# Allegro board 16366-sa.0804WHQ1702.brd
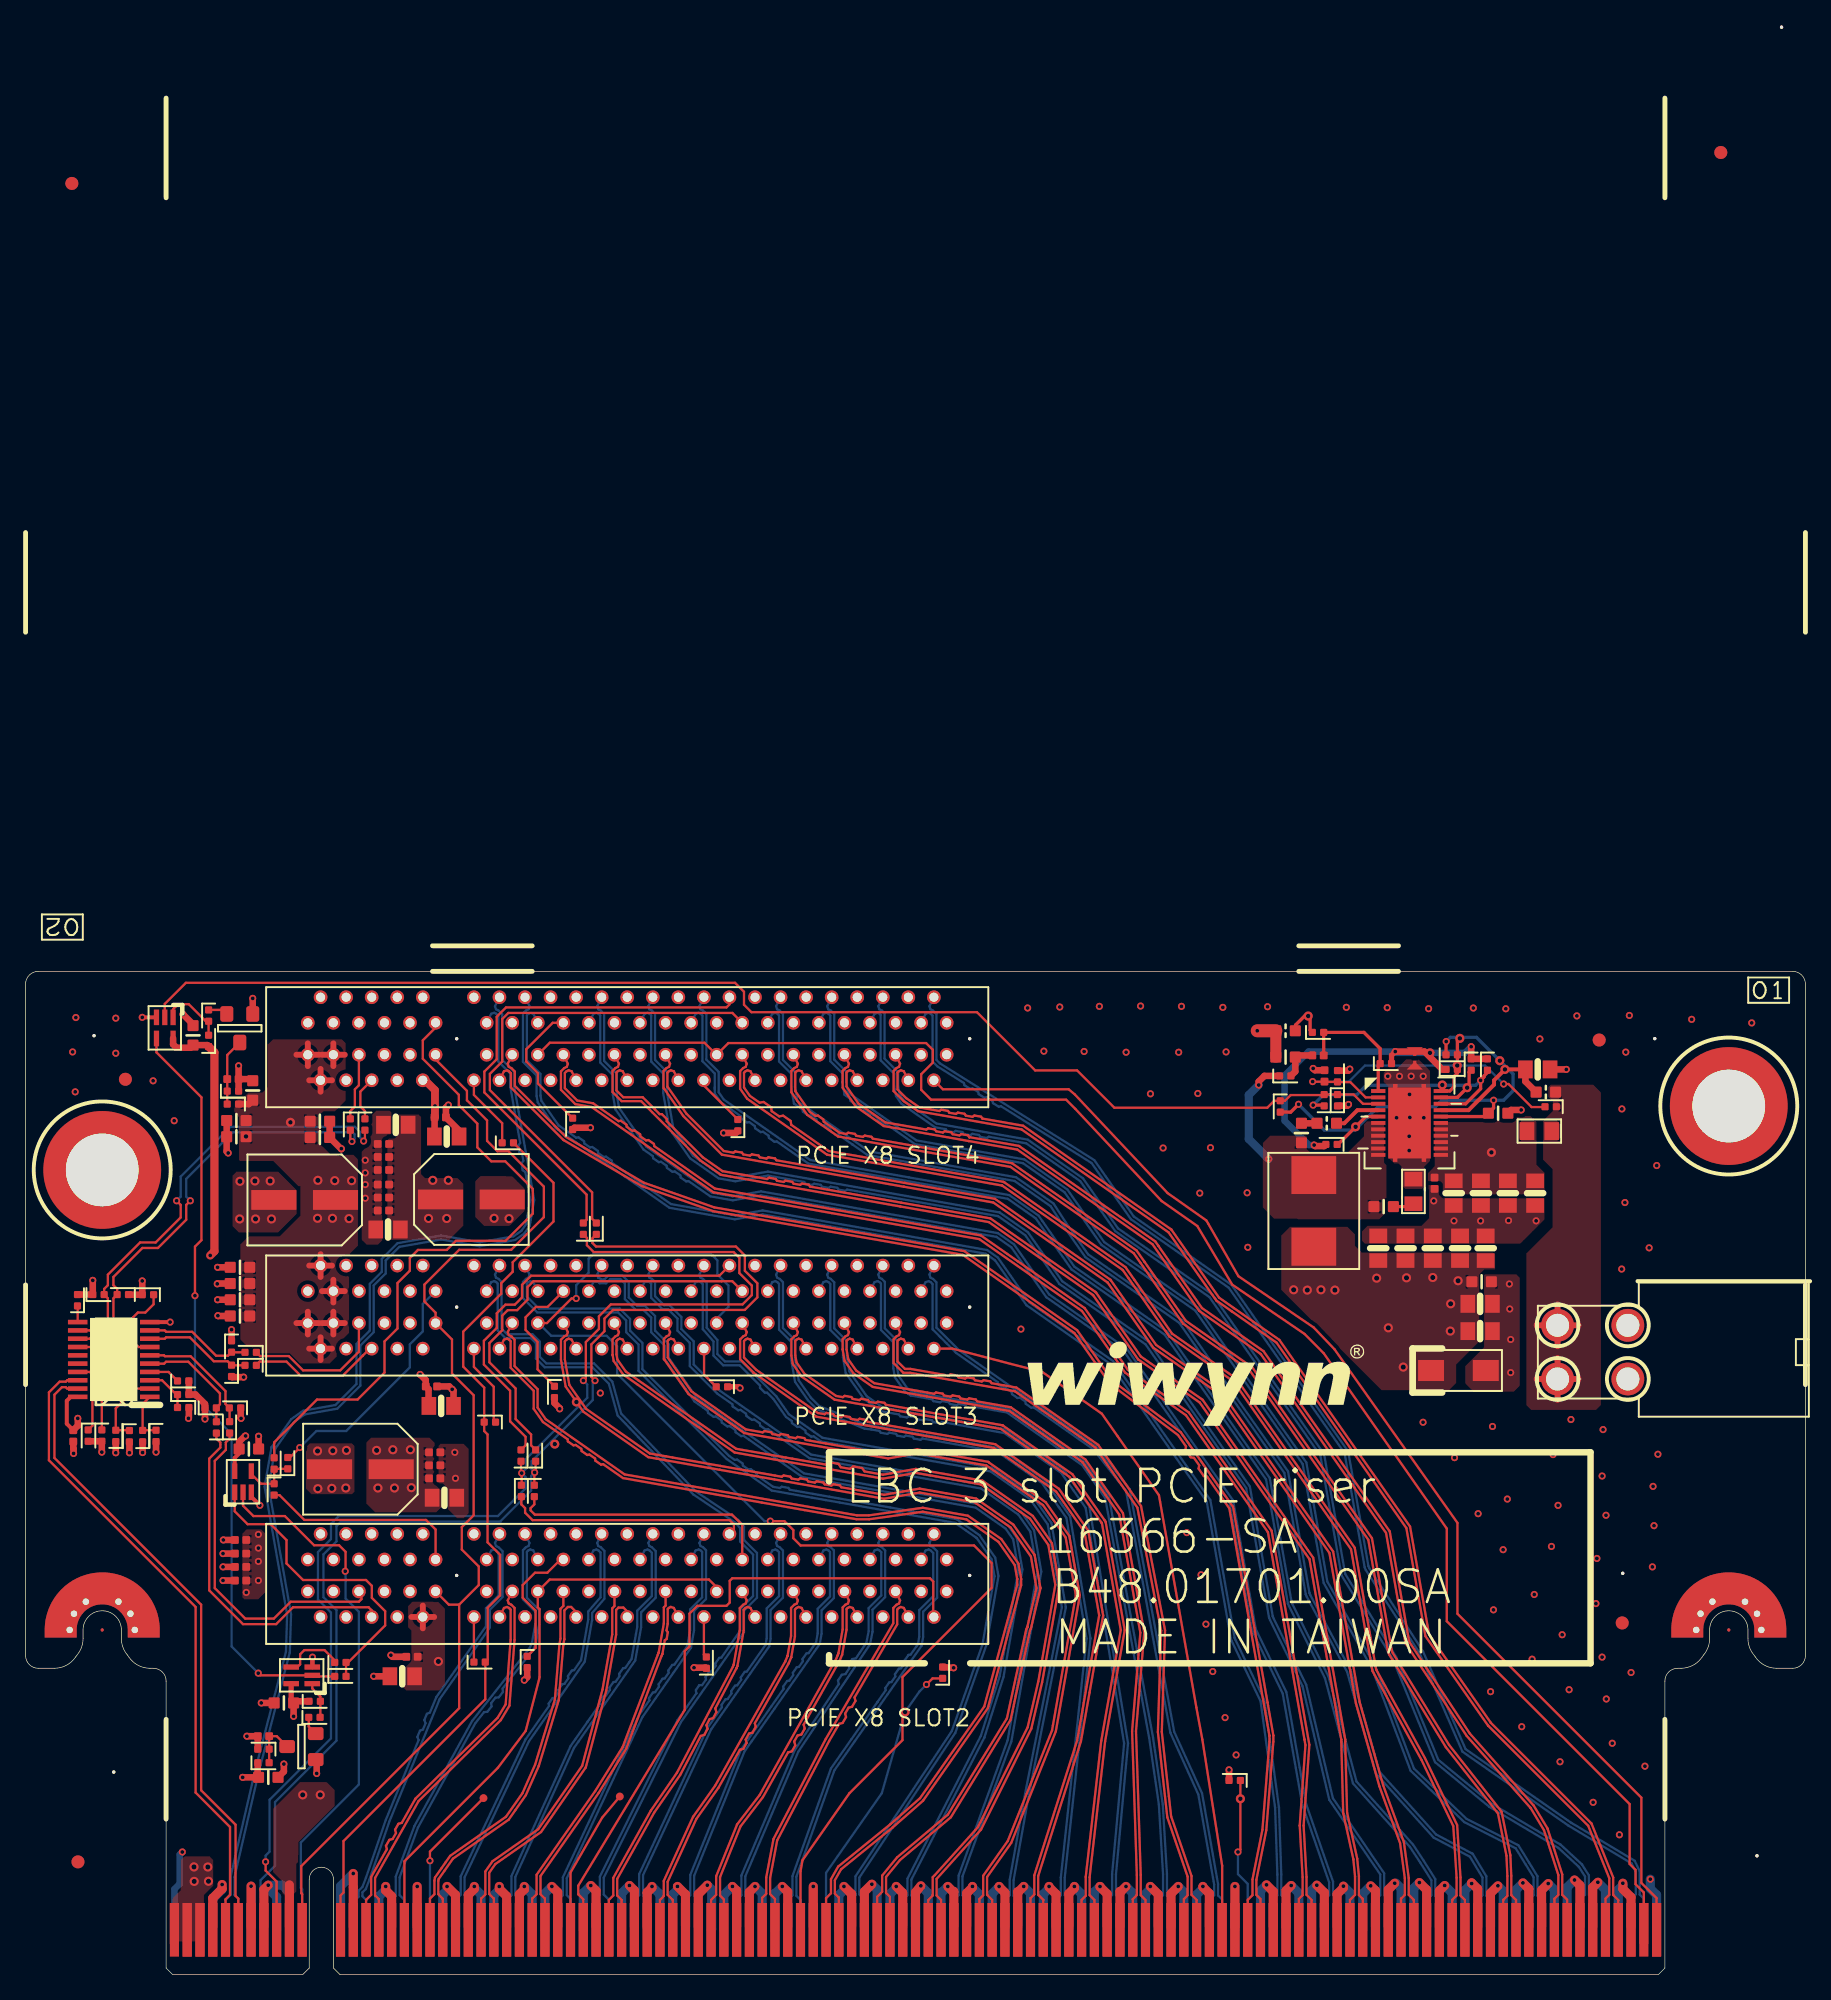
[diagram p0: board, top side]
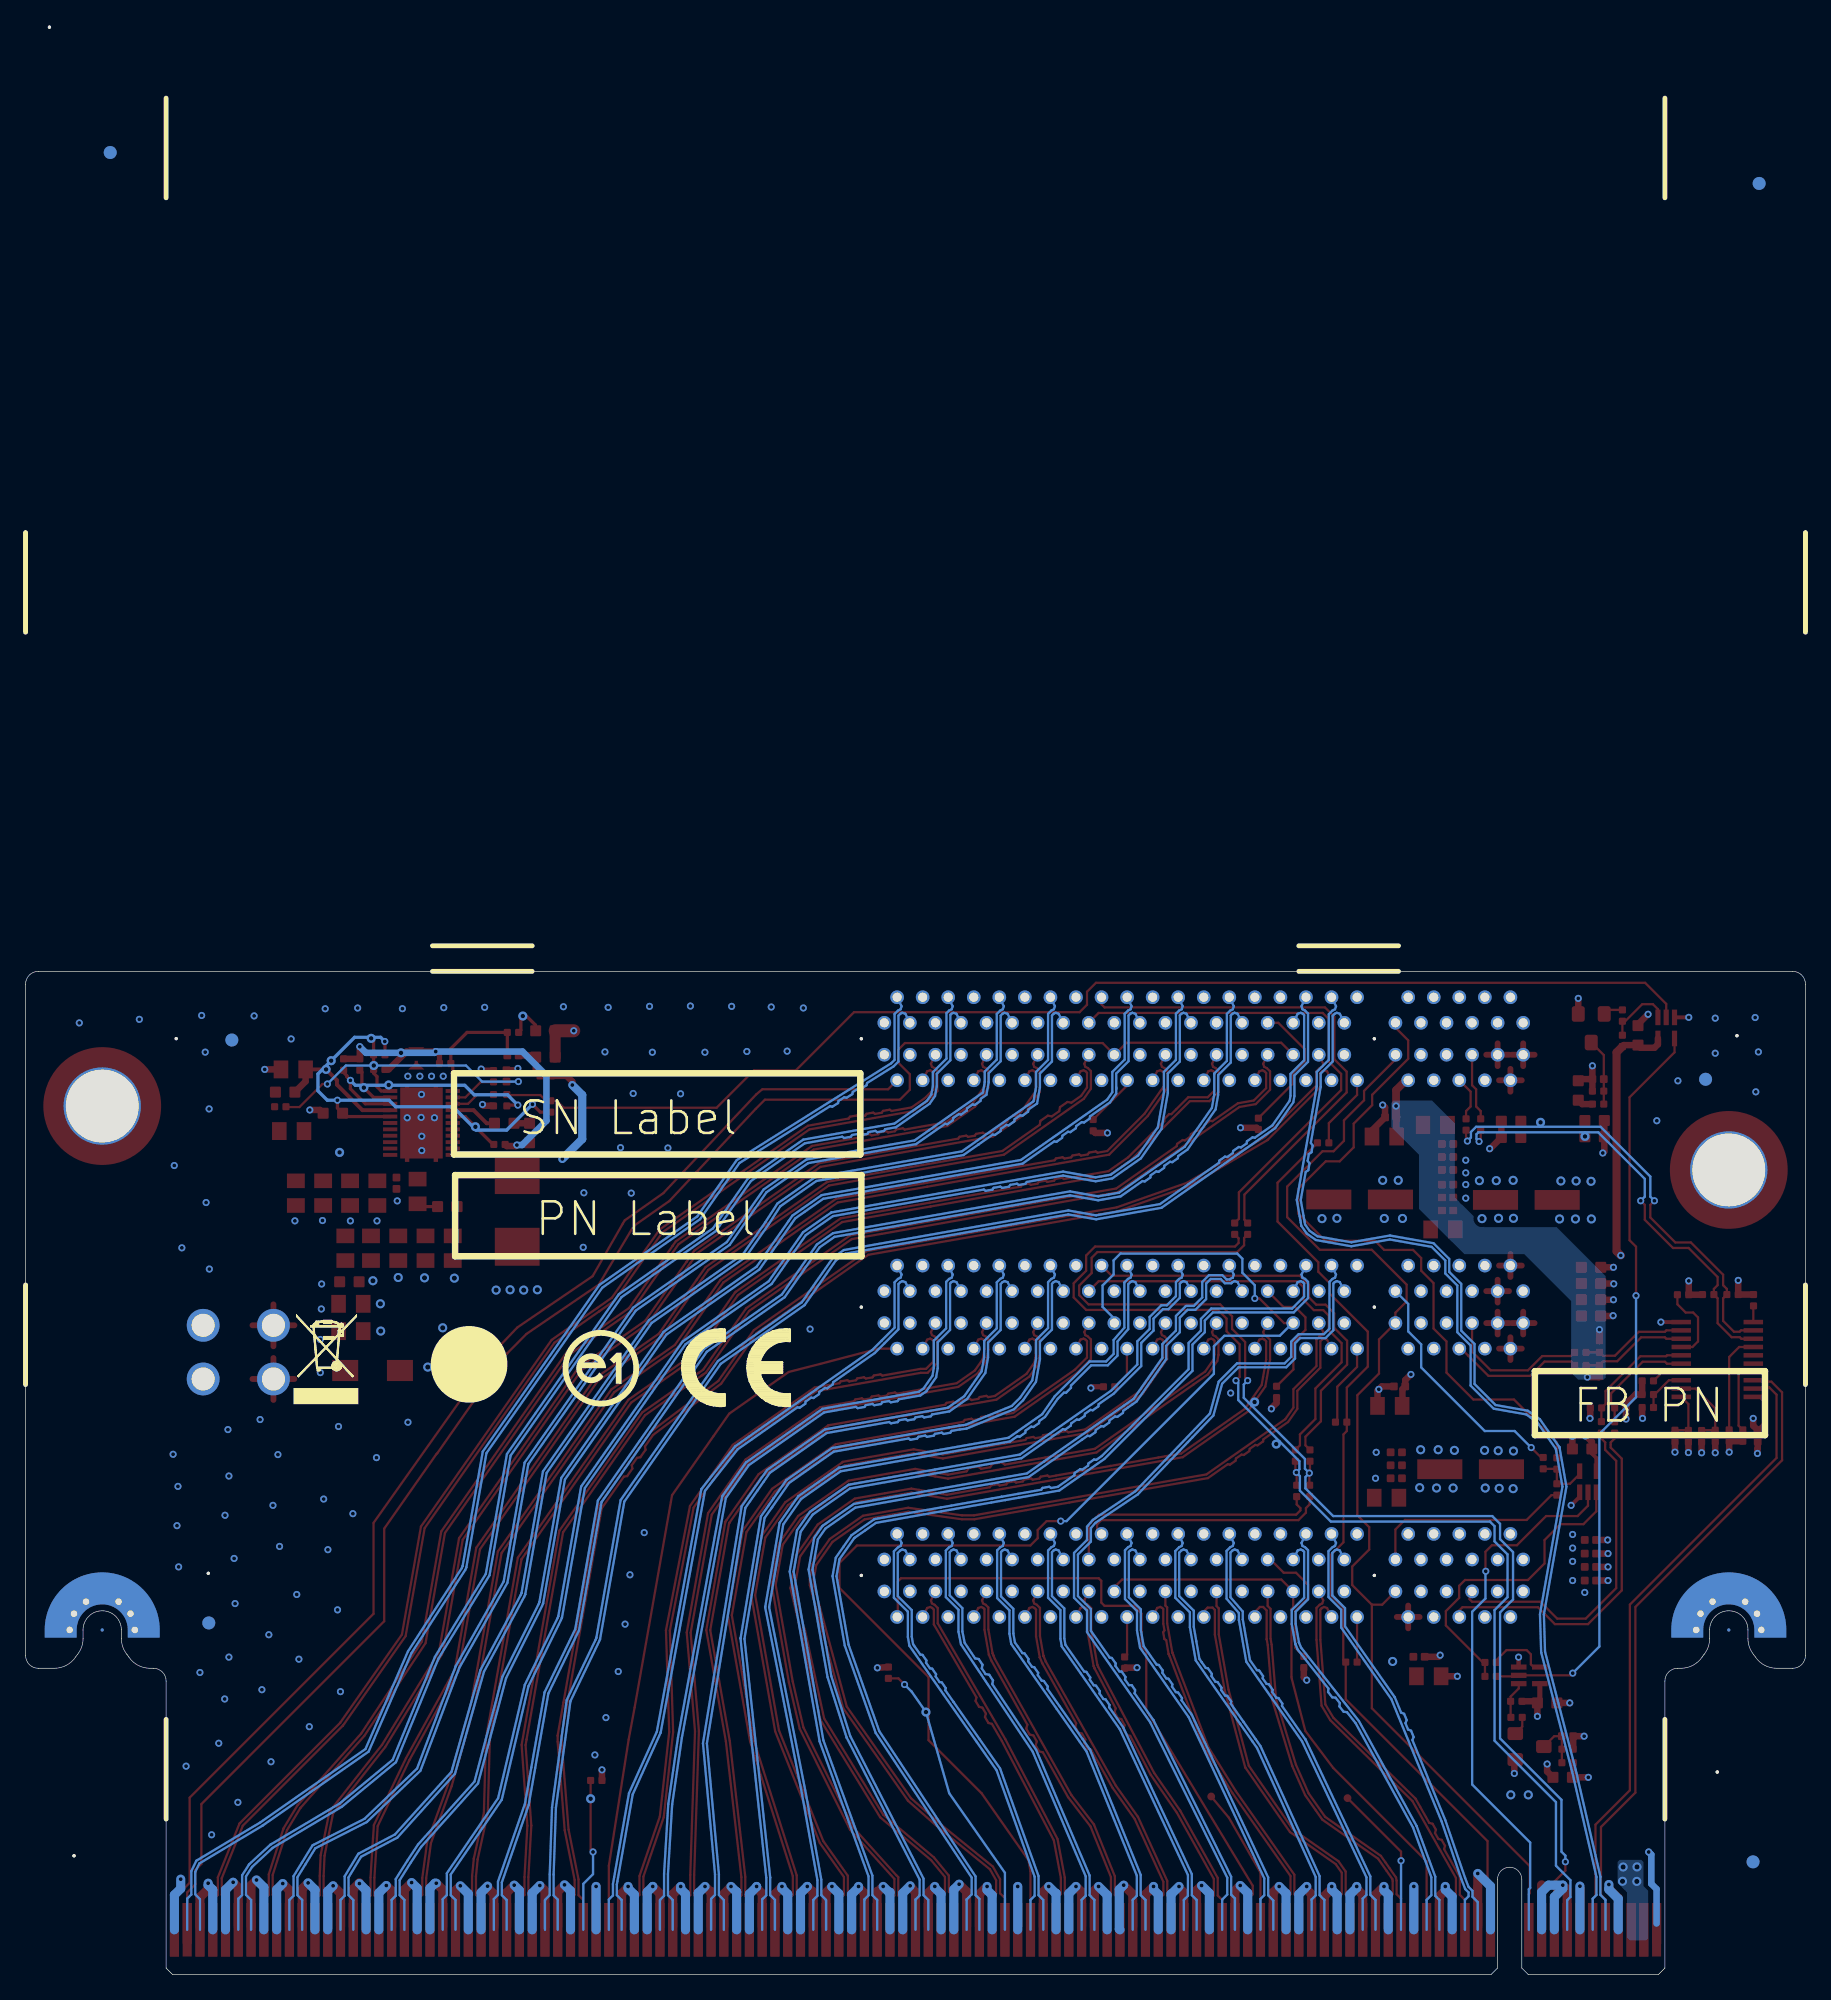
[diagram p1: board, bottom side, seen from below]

Outline 139.3 x 78.5 mm; copper layers: TOP, L2GND, L3, L4, L5GND, BOTTOM. Coordinates in mm from the lower left corner of the outline.
Outline path: 0,77.5 0,24.96 arc(0.29,24.25) 1,23.96 2.26,23.96 arc(3.2,24.2) 3.92,24.85 arc(3.99,24.94) 4.06,25.03 arc(4.39,25.62) 4.5,26.29 4.5,26.96 arc(6,28.46) 7.5,26.96 7.5,26.29 arc(7.61,25.62) 7.94,25.03 arc(8.01,24.94) 8.08,24.85 arc(8.8,24.2) 9.74,23.96 10,23.96 arc(10.71,23.67) 11,22.96 11,0.5 11.5,0 21.7,0 22.2,0.5 22.2,7.45 arc(23.15,8.4) 24.1,7.45 24.1,0.5 24.6,0 127.8,0 128.3,0.5 128.3,22.96 arc(128.59,23.67) 129.3,23.96 129.56,23.96 arc(130.5,24.2) 131.22,24.85 arc(131.29,24.94) 131.36,25.03 arc(131.69,25.62) 131.8,26.29 131.8,26.96 arc(133.3,28.46) 134.8,26.96 134.8,26.29 arc(134.91,25.62) 135.24,25.03 arc(135.31,24.94) 135.38,24.85 arc(136.1,24.2) 137.04,23.96 138.3,23.96 arc(139.01,24.25) 139.3,24.96 139.3,77.5 arc(139.01,78.21) 138.3,78.5 1,78.5 arc(0.29,78.21) 0,77.5 ; 3.2,62.96 arc(6,65.76) 8.8,62.96 arc(6,60.16) 3.2,62.96 ; 133.3,70.76 arc(136.1,67.96) 133.3,65.16 arc(130.5,67.96) 133.3,70.76

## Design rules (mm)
constraint set DEFAULT: min track width 0.127, pair gap 0.102
net group POWER_3V3: nets P3V3_SNB P3V3_VFB
net group POWER_BOOT_20_30: nets P3V3_VBST P3V3_VBST_RC
net group PWRGD_ENA_RST_50_12_12: nets P3V3_EN P3V3_PG
net group ADC_10_15: nets AGND_P3V3
net group MISC: nets ADDR_0 ADDR_1 ADDR_2 INTRPT INTRPT_0 INTRPT_1 INTRPT_2 INTRPT_3 LAN_SMB_ALERT_N PCIE_SLOT0_CPRSNT1_N PCIE_SLOT0_CPRSNT2_N PCIE_SLOT1_CPRSNT1_N PCIE_SLOT1_CPRSNT2_N PCIE_SLOT2_CPRSNT1_N PCIE_SLOT2_CPRSNT2_N PCIE_WAKE_N RSVD0 RSVD1 S0_SMB_ALERT_B12_N S1_SMB_ALERT_B12_N S2_SMB_ALERT_B12_N SLOT0_CONFIG SLOT0_ID_0 SLOT0_ID_1 SLOT1_CONFIG SLOT1_ID_0 SLOT1_ID_1 SLOT2_ID_0 SLOT2_ID_1
net group MISC_50_20_12: nets PCH_PLTRST_N PERST_O_1_R PERST_O_2_R PERST_P12V_MB_Y_N PERST_P12V_R_N PERST_P12V_Y_N PERST_SLOT0_N PERST_SLOT1_N PERST_SLOT2_N PERST_SLOT_N RESET_O_1 RESET_O_2 RESET_P12V_IN RESET_P12V_MB_IN
net group POWER_PHASE_GATE_25_20: nets P3V3_LL_R
net group POWER_SIGNAL_10_20: nets P3V3_MODE P3V3_RF P3V3_ROVP P3V3_TRIP P3V3_VFB_R P3V3_VREG
net group POWER_VCC_20_20: nets P3V3_VDD
net group PWR: nets P3V3_MB
nets with their own width: min track width 0.508; nets GND

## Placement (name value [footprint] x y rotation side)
C1  SCD1U25V2KX-GP  [C402H22]  16.83 34 270 top
C2  SCD1U25V2KX-GP  [C402H22]  16.83 32.93 270 top
C3  SCD1U25V2KX-GP  [C402H22]  16.83 31.89 270 top
C4  SCD1U25V2KX-GP  [C402H22]  16.83 30.83 270 top
C5  SCD1U16V2KX-3GP  [C402H22]  32.02 39.84 90 top
C6  SCD1U16V2KX-3GP  [C402H22]  32.02 38.83 90 top
C7  SCD1U16V2KX-3GP  [C402H22]  32.02 40.86 90 top
C8  SC10U6D3V5KX-4GP  [C805H58]  29.48 23.33 270 top
C9  SCD1U16V2KX-3GP  [C402H22]  30.24 24.86 270 top
C10  SCD1U25V3KX-GP  [C603H36]  16.78 54.07 270 top
C11  SCD1U25V3KX-GP  [C603H36]  16.78 51.53 270 top
C12  SCD1U25V3KX-GP  [C603H36]  16.78 52.8 270 top
C13  SCD1U25V3KX-GP  [C603H36]  16.78 55.34 270 top
C14  SCD1U16V2KX-3GP  [C402H22]  28.01 59.78 270 top
C15  SCD1U16V2KX-3GP  [C402H22]  28.01 61.82 270 top
C16  SCD1U16V2KX-3GP  [C402H22]  28.01 60.8 270 top
C17  SC10U6D3V5KX-4GP  [C805H58]  32.53 44.49 90 top
C18  SCD1U16V2KX-3GP  [C402H22]  31.77 46.02 90 top
C19  SCD01U16V2KX-3GP  [C402H22]  18.62 18.65 270 top
C20  SCD1U25V3KX-GP  [C603H36]  20.22 21.25 270 top
C21  SCD1U25V3KX-GP  [C603H36]  19 15.43 90 top
C22  SCD1U25V3KX-GP  [C603H36]  13.11 73.49 180 top
C23  SCD1U25V3KX-GP  [C603H36]  17.78 69.18 180 top
C24  SCD1U16V2KX-3GP  [C402H22]  3.73 42.15 180 top
C25  SCD1U25V3KX-GP  [C603H36]  16.5 66.83 270 top
C26  SCD1U16V2KX-3GP  [C402H22]  32.46 67.07 90 top
C27  SC10U6D3V5KX-4GP  [C805H58]  32.96 65.58 90 top
C28  SCD1U25V3KX-GP  [C603H36]  16.5 65.56 270 top
C29  SCD1U25V3KX-GP  [C603H36]  23.04 66.77 90 top
C30  SCD1U25V3KX-GP  [C603H36]  23.04 65.5 90 top
C31  SCD1U16V2KX-3GP  [C402H22]  28.01 63.97 270 top
C32  SCD1U16V2KX-3GP  [C402H22]  28.01 62.96 270 top
C33  SCD1U16V2KX-3GP  [C402H22]  28.01 64.99 270 top
C34  SC10U6D3V5KX-4GP  [C805H58]  32.78 37.3 90 top
C35  SC10U6D3V5KX-4GP  [C805H58]  28.37 58.3 270 top
C36  SC10U6D3V5KX-4GP  [C805H58]  28.97 66.49 270 top
C37  SCD01U16V2KX-3GP  [C402H22]  16.23 70.07 90 top
C40  SCD1U25V3KX-GP  [C603H36]  17.48 41.12 90 top
CN1  PCISLT98-79-GP  [G630H9811210TEU]  33.74 31.22 0 top
CN2  PCISLT98-79-GP  [G630H9811210TEU]  33.74 52.23 0 top
CN3  PCISLT98-79-GP  [G630H9811210TEU]  33.74 73.23 0 top
CN4  ALP-CONN4F-GP  [C23118-P04C0-L]  122.65 48.7 90 top
GF1  GF-PCIE-230P-GP  [GF-PCIE-230P]  23.15 1.4 0 top
H1  STFT363B238R224H453-GP  [STFT363B238R224H453]  6 62.96 180 top
H2  STFT363B238R224H453-GP  [STFT363B238R224H453]  133.3 67.96 180 top
H3  GEN276X162R197X296-6-F-A-GP  [GEN276X162R197X296-6-F-A]  6 26.96 0 top
H4  GEN276X162R197X296-6-F-A-GP  [GEN276X162R197X296-6-F-A]  133.3 26.96 0 top
NOREF  -  []  0 23.96 0 top
NOREF#2  *  [unnamed#2]  3.62 140.16 0 top
NOREF#3  *  [unnamed#2]  7.82 70.05 0 top
NOREF#4  *  [unnamed#2]  124.96 27.51 0 top
NOREF#5  -  []  92.02 46.21 0 top
NOREF#6  -  []  2.88 81.97 180 top
NOREF#7  -  []  0 23.96 0 top
NOREF#8  *  [unnamed#2]  4.1 8.81 0 top
NOREF#9  -  []  -5 145.85 0 top
NOREF#10  -  []  -118.09 -28.02 0 top
NOREF#11  *  [unnamed#2]  132.67 142.58 0 top
NOREF#12  -  [unnamed#2]  5.36 73.46 0 top
NOREF#13  -  []  0 23.96 0 top
NOREF#14  *  [unnamed#2]  123.16 73.13 0 top
NOREF#15  -  [unnamed#2]  127.51 73.24 0 top
NOREF#16  -  [unnamed#2]  125 31.39 0 top
NOREF#17  -  [unnamed#2]  137.43 152.39 0 top
NOREF#18  -  [unnamed#2]  135.51 9.29 0 top
NOREF#19  -  []  136.42 77.03 0 top
NOREF#20  -  [unnamed#2]  6.9 15.84 0 top
NOREF#21  -  []  87.9 47.44 180 bottom
NOREF#22  -  []  104.59 47.74 180 bottom
NOREF#23  *  [unnamed#2]  132.67 142.58 180 bottom
NOREF#24  *  [unnamed#2]  124.96 27.51 180 bottom
NOREF#25  -  []  115.79 49.07 180 bottom
NOREF#26  *  [unnamed#2]  4.1 8.81 180 bottom
NOREF#27  *  [unnamed#2]  7.82 70.05 180 bottom
NOREF#28  *  [unnamed#2]  123.16 73.13 180 bottom
NOREF#29  -  []  94.28 47.44 180 bottom
NOREF#30  *  [unnamed#2]  3.62 140.16 180 bottom
PC485  SC470P50V2KX-3GP  [C402H22]  101.15 71.92 90 top
PC790  SC22U6D3V5MX-5-GP  [C805H56]  105.87 56.83 180 top
PC792  SC22U6D3V5MX-5-GP  [C805H56]  108 56.83 180 top
PC793  SC22U6D3V5MX-5-GP  [C805H56]  110.13 56.83 180 top
PC794  SC22U6D3V5MX-5-GP  [C805H56]  112.27 56.83 180 top
PC795  SC22U6D3V5MX-5-GP  [C805H56]  114.27 56.83 180 top
PC836  SC22U6D3V5MX-5-GP  [C805H56]  113.84 52.48 90 top
PC904  SC10U16V5KX-1-GP  [C805H54]  116.01 61.14 0 top
PC905  SC10U16V5KX-1-GP  [C805H54]  118.14 61.14 0 top
PC906  SC10U16V5KX-1-GP  [C805H54]  111.77 61.14 0 top
PC907  SCD1U16V2KX-3GP  [C402H22]  110.27 61.92 0 top
PC908  SCD1U16V3KX-3GP  [C603H36]  113.96 54.21 90 top
PC909  SC22U6D3V5MX-5-GP  [C805H56]  113.84 50.35 90 top
PC911  SC10U16V5KX-1-GP  [C805H54]  113.9 61.14 0 top
PC917  SCD1U50V3KX-GP  [C603H36]  99.86 65.85 0 top
PC918  SC2K2P50V3KX-GP  [C603]  106.29 60.09 90 top
PC919  SCD1U50V3KX-GP  [C603H36]  98.61 71.79 90 top
PC941  SC4D7U25V5KX-1-GP  [C805H58]  118.35 70.83 90 top
PC942  SC1U16V3KX-5GP  [C603H36]  115.25 67.4 270 top
PC1055  SC1U10V2KX-4-GP  [C402H22]  101.66 70.32 180 top
PD11  PTZ5D6B-GP  [D502715AKH87]  112.14 47.26 270 top
PG64  COPPER-CLOSE-GP-U  [CON2C-U]  108.72 71.69 0 top
PL49  IND-1UH-188-GP  [L7166-1830-UH197]  100.82 59.75 0 top
PL50  BLM21PG220SN1DGP  [L20125H42]  118.47 66 270 top
PR2  147KR2F-L-GP  [R402H16]  113.14 71.21 0 top
PR3  309KR2F-GP  [R402H16]  111.62 71.97 90 top
PR4  309KR2F-GP  [R402H16]  111.62 70.83 90 top
PR36  3K74R2F-GP  [R402H16]  102.68 70.29 180 top
PR347  20KR2F-L-GP  [R402H16]  102.68 68.41 180 top
PR441  10KR2F-2-GP  [R402H16]  98.2 67.93 0 top
PR481  2D7R3-GP  [R603H22]  101.84 66.61 270 top
PR540  19K6R2F-GP  [R402H16]  119.36 67.91 270 top
PR633  10R3F-GP  [R603H22]  98.61 73.85 90 top
PR635  45K3R2F-L-GP  [R402H16]  101.15 73.72 90 top
PR638  10KR2F-2-GP  [R402H16]  106.46 71.28 90 top
PR640  2KR2F-3-GP  [R402H16]  98.59 70.32 90 top
PR642  3D01R5F-GP  [R805H24]  108.62 61.28 180 top
PR649  2D2R3-1-U-GP  [R603H22]  118.98 69.05 270 top
PR817  0R2J-2-GP  [R402H16]  102.21 64.96 270 top
PR2171  39K2R2F-L-GP  [R402H16]  114.41 71.21 0 top
PR2172  39K2R2F-L-GP  [R402H16]  101.63 68.41 180 top
PU54  TPS53319DQPR-GP  [QFN22G6050-G6133H60]  108.31 66.64 90 top
R1  8K2R2F-1-GP  [R402H16]  18.62 16.57 90 top
R2  3K3R2F-2-GP  [R402H16]  18.62 17.63 270 top
R3  0R2J-2-GP  [R402H16]  22.61 20.12 90 top
R4  0R2J-2-GP  [R402H16]  14.33 75.04 0 top
R5  8K2R2F-1-GP  [R402H16]  16.23 68.11 270 top
R7  100R2J-L-GP  [R402H15]  39.26 24.45 0 top
R8  100R2J-L-GP  [R402H15]  53.28 24.4 180 top
R9  100R2J-L-GP  [R402H15]  54.5 45.99 270 top
R10  100R2J-L-GP  [R402H15]  41.39 45.59 0 top
R11  100R2J-L-GP  [R402H15]  55.74 66.46 180 top
R12  100R2J-L-GP  [R402H15]  42.82 66.57 0 top
R13  10KR2F-2-GP  [R402H16]  12.34 46.45 90 top
R14  10KR2F-2-GP  [R402H16]  9.58 53.2 270 top
R15  10KR2F-2-GP  [R402H16]  4.06 52.76 180 top
R16  10KR2F-2-GP  [R402H16]  5.97 42.17 0 top
R17  10KR2F-2-GP  [R402H16]  4.9 42.17 0 top
R18  4K7R2J-2-GP  [R402H16]  16.39 44.34 270 top
R19  4K7R2J-2-GP  [R402H16]  16.12 49.14 0 top
R20  4K7R2J-2-GP  [R402H16]  7.61 53.21 270 top
R21  4K7R2J-2-GP  [R402H16]  14.49 44.34 90 top
R22  4K7R2J-2-GP  [R402H16]  16.12 47.24 180 top
R23  4K7R2J-2-GP  [R402H16]  5.71 53.21 90 top
R24  3K3R2F-2-GP  [R402H16]  16.23 69.13 90 top
R26  10KR2F-2-GP  [R402H16]  12.34 44.37 270 top
R27  10KR2F-2-GP  [R402H16]  7.06 42.15 180 top
R28  10KR2F-2-GP  [R402H16]  9.16 42.13 180 top
R29  10KR2F-2-GP  [R402H16]  10.21 42.15 0 top
R30  10KR2F-2-GP  [R402H16]  8.13 42.12 0 top
R31  10KR2F-2-GP  [R402H16]  12.34 45.38 90 top
R33  1KR2J-1-GP  [R402H16]  71.77 23.61 180 top
R35  1KR2J-1-GP  [R402H16]  94.63 15.18 270 top
R36  4K7R2J-2-GP  [R402H16]  14.33 73.06 180 top
R37  4K7R2J-2-GP  [R402H16]  22.63 21.38 90 top
R38  0R2J-2-GP  [R402H16]  20.52 40.01 180 top
R39  0R2J-2-GP  [R402H16]  19.46 37.96 0 top
R40  0R2J-2-GP  [R402H16]  19.46 39.99 180 top
R41  0R2J-2-GP  [R402H16]  24.64 24.42 90 top
R42  0R2J-2-GP  [R402H16]  24.64 23.33 90 top
RE1  0R2J-2-GP  [R402H16]  15.97 42.82 180 top
RE2  0R2J-2-GP  [R402H16]  38.8 37.84 0 top
RE3  0R2J-2-GP  [R402H16]  39.82 37.84 0 top
RE4  0R2J-2-GP  [R402H16]  35.53 24.44 90 top
RE5  0R2J-2-GP  [R402H16]  36.34 43.22 270 top
RE6  0R2J-2-GP  [R402H16]  17.62 48.68 270 top
RE7  0R2J-2-GP  [R402H16]  14.94 42.81 180 top
RE8  0R2J-2-GP  [R402H16]  17.62 47.67 270 top
RE9  0R2J-2-GP  [R402H16]  38.78 40.61 180 top
RE10  0R2J-2-GP  [R402H16]  39.92 40.61 180 top
RE11  0R2J-2-GP  [R402H16]  37.74 65.08 90 top
RE12  0R2J-2-GP  [R402H16]  25.42 66.51 0 top
RE13  0R2J-2-GP  [R402H16]  26.56 66.51 0 top
RE14  0R2J-2-GP  [R402H16]  43.65 58.36 180 top
RE15  0R2J-2-GP  [R402H16]  44.67 58.36 180 top
TC1  SE100U16VM-10GP  [SE351618H217]  21.84 60.61 270 top
TC2  SE100U16VM-10GP  [SE351618H217]  34.89 60.65 90 top
TC3  SE100U16VM-10GP  [SE351618H217]  26.2 39.54 270 top
TP6  -  [TPAD24]  46.51 13.93 0 top
TP7  -  [TPAD24]  35.84 13.8 0 top
U1  TPS3809K33-2-GP  [SOT-23-1H58]  21.59 17.83 90 top
U2  TPS3809K33-2-GP  [SOT-23-1H58]  16.76 74.05 180 top
U8  SNLVC1G08DCKRG4-GP  [SC70-5H44]  21.61 23.41 270 top
U9  SNLVC1G08DCKRG4-GP  [SC70-5H44]  10.9 74.07 0 top
U10  PCA9544APW-GP  [TSOIC20H44]  6.9 48.13 90 top
U13  SNLVC1G08DCKRG4-GP  [SC70-5H44]  17.02 38.56 180 top

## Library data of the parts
C1-C4 = C402H22: tolerance: 78.10422.5FL
C5-C7 C9 C14-C16 C18 C24 C26 C31-C33 PC907 = C402H22: tolerance: 78.10421.2FL
C8 C17 C27 C34-C36 = C805H58: tolerance: 78.10620.21L
C10-C13 C20-C23 C25 C28-C30 C40 = C603H36: tolerance: 78.10422.2BL
C19 C37 = C402H22: tolerance: 78.10321.2FL
CN1-CN3 = G630H9811210TEU: tolerance: 020.50107.0098
CN4 = C23118-P04C0-L: tolerance: 020.80390.0004
GF1 = GF-PCIE-230P: tolerance: ZZ.GF001.711; alternate symbols: (TOP:GF-PCIE-230P)
H1 H2 = STFT363B238R224H453: tolerance: 086.2AT24.04R6
H3 H4 = GEN276X162R197X296-6-F-A: tolerance: ZZ.SCREW.511
PC485 = C402H22: tolerance: 78.47124.2FL
PC790 PC792-PC795 PC836 PC909 = C805H56: tolerance: 78.22610.81L
PC904-PC906 PC911 = C805H54: tolerance: 78.10621.81L
PC908 = C603H36: tolerance: 78.10421.2BL
PC917 PC919 = C603H36: tolerance: 78.10424.2BL
PC918 = C603: tolerance: 78.22224.2BL
PC941 = C805H58: tolerance: 078.47522.0211
PC942 = C603H36: tolerance: 78.10521.2BL
PC1055 = C402H22: tolerance: 78.10523.8FL
PD11 = D502715AKH87: tolerance: 83.5R603.H3H
PG64 = CON2C-U: tolerance: ZZ.CON2C.XXX
PL49 = L7166-1830-UH197: tolerance: 68.1R01E.10D
PL50 = L20125H42: tolerance: 68.00084.831
PR2 = R402H16: tolerance: 64.14735.L1L
PR3 PR4 = R402H16: tolerance: 64.30935.6DL
PR36 = R402H16: tolerance: 64.37415.6DL
PR347 = R402H16: tolerance: 64.20025.6DL
PR441 PR638 R13-R17 R26-R31 = R402H16: tolerance: 64.10025.6DL
PR481 = R603H22: tolerance: 63.2R734.15L
PR540 = R402H16: tolerance: 64.19625.6DL
PR633 = R603H22: tolerance: 64.10R05.55L
PR635 = R402H16: tolerance: 64.45325.6DL
PR640 = R402H16: tolerance: 64.20015.6DL
PR642 = R805H24: tolerance: 64.3R015.16L
PR649 = R603H22: tolerance: 64.2R205.55L
PR817 R3 R4 R38-R42 RE1-RE15 = R402H16: tolerance: 63.R0034.1DL
PR2171 PR2172 = R402H16: tolerance: 64.39225.6DL
PU54 = QFN22G6050-G6133H60: tolerance: 74.53319.073
R1 R5 = R402H16: tolerance: 64.82015.6DL
R2 R24 = R402H16: tolerance: 64.33015.6DL
R7-R12 = R402H15: tolerance: 63.10134.L0L
R18-R23 R36 R37 = R402H16: tolerance: 63.47234.1DL
R33 R35 = R402H16: tolerance: 63.10234.1DL
TC1-TC3 = SE351618H217: tolerance: 79.1071D.3AL
TP6 TP7 = TPAD24: tolerance: ZZ.PAD24.001
U1 U2 = SOT-23-1H58: tolerance: 74.03809.07B
U8 U9 U13 = SC70-5H44: tolerance: 73.01G08.DHG
U10 = TSOIC20H44: tolerance: 71.09544.A0W

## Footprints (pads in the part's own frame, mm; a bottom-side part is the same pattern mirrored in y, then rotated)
C402H22
  custom 0.152x0.152 smd: 1(0,0.445) 2(0,-0.445)
C603
  custom 0.216x0.216 smd: 1(0,0.762) 2(0,-0.762)
C603H36
  custom 0.216x0.216 smd: 1(0,0.762) 2(0,-0.762)
C805H54
  rect 1.397x1.143 smd: 1(0,0.965) 2(0,-0.965)
C805H56
  rect 1.397x1.143 smd: 1(0,0.965) 2(0,-0.965)
C805H58
  rect 1.397x1.143 smd: 1(0,0.965) 2(0,-0.965)
C23118-P04C0-L
  round 2.565 hole 1.803: 1(2.1,-2.75) 2(-2.1,-2.75) 3(2.1,2.75) 4(-2.1,2.75)
CON2C-U
  custom 0.171x0.171 smd: 1(0,0.533) 2(0,-0.533)
D502715AKH87
  rect 1.651x2.032 smd: A(0,2.142) K(0,-2.142)
G630H9811210TEU
  round 0.254 hole 2.362 unplated: (0,0) (40.15,0)
  round 1.067 hole 0.711: A1(-11.65,1.25) A2(-10.65,3.25) A3(-9.65,1.25) A4(-8.65,3.25) A5(-7.65,1.25) A6(-6.65,3.25) A7(-5.65,1.25) A8(-4.65,3.25) A9(-3.65,1.25) A10(-2.65,3.25) A11(-1.65,1.25) A12(1.35,3.25) A13(2.35,1.25) A14(3.35,3.25) A15(4.35,1.25) A16(5.35,3.25) A17(6.35,1.25) A18(7.35,3.25) A19(8.35,1.25) A20(9.35,3.25) A21(10.35,1.25) A22(11.35,3.25) A23(12.35,1.25) A24(13.35,3.25) A25(14.35,1.25) A26(15.35,3.25) A27(16.35,1.25) A28(17.35,3.25) A29(18.35,1.25) A30(19.35,3.25) A31(20.35,1.25) A32(21.35,3.25) A33(22.35,1.25) A34(23.35,3.25) A35(24.35,1.25) A36(25.35,3.25) A37(26.35,1.25) A38(27.35,3.25) A39(28.35,1.25) A40(29.35,3.25) A41(30.35,1.25) A42(31.35,3.25) A43(32.35,1.25) A44(33.35,3.25) A45(34.35,1.25) A46(35.35,3.25) A47(36.35,1.25) A48(37.35,3.25) A49(38.35,1.25) B1(-11.65,-1.25) B2(-10.65,-3.25) B3(-9.65,-1.25) B4(-8.65,-3.25) B5(-7.65,-1.25) B6(-6.65,-3.25) B7(-5.65,-1.25) B8(-4.65,-3.25) B9(-3.65,-1.25) B10(-2.65,-3.25) B11(-1.65,-1.25) B12(1.35,-3.25) B13(2.35,-1.25) B14(3.35,-3.25) B15(4.35,-1.25) B16(5.35,-3.25) B17(6.35,-1.25) B18(7.35,-3.25) B19(8.35,-1.25) B20(9.35,-3.25) B21(10.35,-1.25) B22(11.35,-3.25) B23(12.35,-1.25) B24(13.35,-3.25) B25(14.35,-1.25) B26(15.35,-3.25) B27(16.35,-1.25) B28(17.35,-3.25) B29(18.35,-1.25) B30(19.35,-3.25) B31(20.35,-1.25) B32(21.35,-3.25) B33(22.35,-1.25) B34(23.35,-3.25) B35(24.35,-1.25) B36(25.35,-3.25) B37(26.35,-1.25) B38(27.35,-3.25) B39(28.35,-1.25) B40(29.35,-3.25) B41(30.35,-1.25) B42(31.35,-3.25) B43(32.35,-1.25) B44(33.35,-3.25) B45(34.35,-1.25) B46(35.35,-3.25) B47(36.35,-1.25) B48(37.35,-3.25) B49(38.35,-1.25)
GEN276X162R197X296-6-F-A
  round 0.254 hole 0.025 unplated: (0,0)
  round 0.864 hole 0.508: 1(2.55,0) 2(2.21,1.27) 3(1.27,2.21) 4(-1.28,2.21) 5(-2.21,1.27) 6(-2.55,0)
GF-PCIE-230P
  rect 0.711x3.2 smd: A1(-11.5,2.591) B114(103.5,2.591)
  rect 0.711x4.191 smd: A2(-10.5,2.095) A3(-9.5,2.095) A4(-8.5,2.095) A5(-7.5,2.095) A6(-6.5,2.095) A7(-5.5,2.095) A8(-4.5,2.095) A9(-3.5,2.095) A10(-2.5,2.095) A11(-1.5,2.095) A12(1.5,2.095) A13(2.5,2.095) A14(3.5,2.095) A15(4.5,2.095) A16(5.5,2.095) A17(6.5,2.095) A18(7.5,2.095) A19(8.5,2.095) A20(9.5,2.095) A21(10.5,2.095) A22(11.5,2.095) A23(12.5,2.095) A24(13.5,2.095) A25(14.5,2.095) A26(15.5,2.095) A27(16.5,2.095) A28(17.5,2.095) A29(18.5,2.095) A30(19.5,2.095) A31(20.5,2.095) A32(21.5,2.095) A33(22.5,2.095) A34(23.5,2.095) A35(24.5,2.095) A36(25.5,2.095) A37(26.5,2.095) A38(27.5,2.095) A39(28.5,2.095) A40(29.5,2.095) A41(30.5,2.095) A42(31.5,2.095) A43(32.5,2.095) A44(33.5,2.095) A45(34.5,2.095) A46(35.5,2.095) A47(36.5,2.095) A48(37.5,2.095) A49(38.5,2.095) A50(39.5,2.095) A51(40.5,2.095) A52(41.5,2.095) A53(42.5,2.095) A54(43.5,2.095) A55(44.5,2.095) A56(45.5,2.095) A57(46.5,2.095) A58(47.5,2.095) A59(48.5,2.095) A60(49.5,2.095) A61(50.5,2.095) A62(51.5,2.095) A63(52.5,2.095) A64(53.5,2.095) A65(54.5,2.095) A66(55.5,2.095) A67(56.5,2.095) A68(57.5,2.095) A69(58.5,2.095) A70(59.5,2.095) A71(60.5,2.095) A72(61.5,2.095) A73(62.5,2.095) A74(63.5,2.095) A75(64.5,2.095) A76(65.5,2.095) A77(66.5,2.095) A78(67.5,2.095) A79(68.5,2.095) A80(69.5,2.095) A81(70.5,2.095) A82(71.5,2.095) A83(72.5,2.095) A84(73.5,2.095) A85(74.5,2.095) A86(75.5,2.095) A87(76.5,2.095) A88(77.5,2.095) A89(78.5,2.095) A90(79.5,2.095) A91(80.5,2.095) A92(81.5,2.095) A93(82.5,2.095) A94(83.5,2.095) A95(84.5,2.095) A96(85.5,2.095) A97(86.5,2.095) A98(87.5,2.095) A99(88.5,2.095) A100(89.5,2.095) A101(90.5,2.095) A102(91.5,2.095) A103(92.5,2.095) A104(93.5,2.095) A105(94.5,2.095) A106(95.5,2.095) A107(96.5,2.095) A108(97.5,2.095) A109(98.5,2.095) A110(99.5,2.095) A111(100.5,2.095) A112(101.5,2.095) A113(102.5,2.095) A114(103.5,2.095) A115(104.5,2.095) B1(-11.5,2.349) B2(-10.5,2.349) B3(-9.5,2.349) B4(-8.5,2.349) B5(-7.5,2.349) B6(-6.5,2.349) B7(-5.5,2.349) B8(-4.5,2.349) B9(-3.5,2.349) B10(-2.5,2.349) B11(-1.5,2.349) B12(1.5,2.349) B13(2.5,2.349) B14(3.5,2.349) B15(4.5,2.349) B16(5.5,2.349) B17(6.5,2.349) B18(7.5,2.349) B19(8.5,2.349) B20(9.5,2.349) B21(10.5,2.349) B22(11.5,2.349) B23(12.5,2.349) B24(13.5,2.349) B25(14.5,2.349) B26(15.5,2.349) B27(16.5,2.349) B28(17.5,2.349) B29(18.5,2.349) B30(19.5,2.349) B31(20.5,2.349) B32(21.5,2.349) B33(22.5,2.349) B34(23.5,2.349) B35(24.5,2.349) B36(25.5,2.349) B37(26.5,2.349) B38(27.5,2.349) B39(28.5,2.349) B40(29.5,2.349) B41(30.5,2.349) B42(31.5,2.349) B43(32.5,2.349) B44(33.5,2.349) B45(34.5,2.349) B46(35.5,2.349) B47(36.5,2.349) B48(37.5,2.349) B49(38.5,2.349) B50(39.5,2.349) B51(40.5,2.349) B52(41.5,2.349) B53(42.5,2.349) B54(43.5,2.349) B55(44.5,2.349) B56(45.5,2.349) B57(46.5,2.349) B58(47.5,2.349) B59(48.5,2.349) B60(49.5,2.349) B61(50.5,2.349) B62(51.5,2.349) B63(52.5,2.349) B64(53.5,2.349) B65(54.5,2.349) B66(55.5,2.349) B67(56.5,2.349) B68(57.5,2.349) B69(58.5,2.349) B70(59.5,2.349) B71(60.5,2.349) B72(61.5,2.349) B73(62.5,2.349) B74(63.5,2.349) B75(64.5,2.349) B76(65.5,2.349) B77(66.5,2.349) B78(67.5,2.349) B79(68.5,2.349) B80(69.5,2.349) B81(70.5,2.349) B82(71.5,2.349) B83(72.5,2.349) B84(73.5,2.349) B85(74.5,2.349) B86(75.5,2.349) B87(76.5,2.349) B88(77.5,2.349) B89(78.5,2.349) B90(79.5,2.349) B91(80.5,2.349) B92(81.5,2.349) B93(82.5,2.349) B94(83.5,2.349) B95(84.5,2.349) B96(85.5,2.349) B97(86.5,2.349) B98(87.5,2.349) B99(88.5,2.349) B100(89.5,2.349) B101(90.5,2.349) B102(91.5,2.349) B103(92.5,2.349) B104(93.5,2.349) B105(94.5,2.349) B106(95.5,2.349) B107(96.5,2.349) B108(97.5,2.349) B109(98.5,2.349) B110(99.5,2.349) B111(100.5,2.349) B112(101.5,2.349) B113(102.5,2.349) B115(104.5,2.349)
L7166-1830-UH197
  rect 3.505x2.972 smd: 1(0,2.805) 2(0,-2.805)
L20125H42
  rect 1.397x1.143 smd: 1(0,0.965) 2(0,-0.965)
QFN22G6050-G6133H60
  rect 0.305x1.118 smd: 1(2.5,2.449) 2(2,2.449) 3(1.5,2.449) 4(1,2.449) 5(0.5,2.449) 6(0,2.449) 7(-0.5,2.449) 8(-1,2.449) 9(-1.5,2.449) 10(-2,2.449) 11(-2.5,2.449) 12(-2.5,-2.449) 13(-2,-2.449) 14(-1.5,-2.449) 15(-1,-2.449) 16(-0.5,-2.449) 17(0,-2.449) 18(0.5,-2.449) 19(1,-2.449) 20(1.5,-2.449) 21(2,-2.449) 22(2.5,-2.449)
  custom 0.832x0.832 smd: 23(0,0)
R402H15
  custom 0.14x0.14 smd: 1(0,0.445) 2(0,-0.445)
R402H16
  custom 0.14x0.14 smd: 1(0,0.445) 2(0,-0.445)
R603H22
  custom 0.216x0.216 smd: 1(0,0.762) 2(0,-0.762)
R805H24
  rect 1.397x1.143 smd: 1(0,0.965) 2(0,-0.965)
SC70-5H44
  rect 0.406x1.219 smd: 1(0.65,0.826) 2(0,0.826) 3(-0.65,0.826) 4(-0.65,-0.826) 5(0.65,-0.826)
SE351618H217
  rect 1.549x3.531 smd: 1(0,2.413) 2(0,-2.413)
SOT-23-1H58
  custom 0.254x0.254 smd: 1(-1.016,-1.118) 2(1.016,-1.118) 3(0,1.118)
STFT363B238R224H453
  round 9.22 hole 5.69: 1(0,0)
TPAD24
  round 0.61 smd: 1(0,0)
TSOIC20H44
  rect 0.356x1.524 smd: 1(-2.926,-2.819) 2(-2.276,-2.819) 3(-1.626,-2.819) 4(-0.975,-2.819) 5(-0.325,-2.819) 6(0.325,-2.819) 7(0.975,-2.819) 8(1.626,-2.819) 9(2.276,-2.819) 10(2.926,-2.819) 11(2.926,2.819) 12(2.276,2.819) 13(1.626,2.819) 14(0.975,2.819) 15(0.325,2.819) 16(-0.325,2.819) 17(-0.975,2.819) 18(-1.626,2.819) 19(-2.276,2.819) 20(-2.926,2.819)
unnamed#2
  round 1.016 smd: (0,0)

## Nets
AGND_P3V3: PG64.1 PR2.1 PR4.1 PR638.2 PR817.2 PR2171.1
GND: C1.2 C2.2 C3.2 C4.2 C5.2 C6.2 C7.2 C8.2 C9.2 C10.2 C11.2 C12.2 C13.2 C14.2 C15.2 C16.2 C17.2 C18.2 C19.2 C20.2 C21.2 C22.2 C23.2 C24.1 C25.2 C26.2 C27.2 C28.2 C29.2 C30.2 C31.2 C32.2 C33.2 C34.2 C35.2 C36.2 C37.2 C40.2 CN1.A1 CN1.A4 CN1.A12 CN1.A15 CN1.A18 CN1.A20 CN1.A23 CN1.A24 CN1.A27 CN1.A28 CN1.A31 CN1.A34 CN1.A37 CN1.A38 CN1.A41 CN1.A42 CN1.A45 CN1.A46 CN1.A49 CN1.B4 CN1.B7 CN1.B13 CN1.B16 CN1.B18 CN1.B21 CN1.B22 CN1.B25 CN1.B26 CN1.B29 CN1.B32 CN1.B35 CN1.B36 CN1.B39 CN1.B40 CN1.B43 CN1.B44 CN1.B47 CN1.B49 CN2.A1 CN2.A4 CN2.A12 CN2.A15 CN2.A18 CN2.A20 CN2.A23 CN2.A24 CN2.A27 CN2.A28 CN2.A31 CN2.A34 CN2.A37 CN2.A38 CN2.A41 CN2.A42 CN2.A45 CN2.A46 CN2.A49 CN2.B4 CN2.B7 CN2.B13 CN2.B16 CN2.B18 CN2.B21 CN2.B22 CN2.B25 CN2.B26 CN2.B29 CN2.B32 CN2.B35 CN2.B36 CN2.B39 CN2.B40 CN2.B43 CN2.B44 CN2.B47 CN2.B49 CN3.A1 CN3.A4 CN3.A12 CN3.A15 CN3.A18 CN3.A20 CN3.A23 CN3.A24 CN3.A27 CN3.A28 CN3.A31 CN3.A34 CN3.A37 CN3.A38 CN3.A41 CN3.A42 CN3.A45 CN3.A46 CN3.A49 CN3.B4 CN3.B7 CN3.B13 CN3.B16 CN3.B18 CN3.B21 CN3.B22 CN3.B25 CN3.B26 CN3.B29 CN3.B32 CN3.B35 CN3.B36 CN3.B39 CN3.B40 CN3.B43 CN3.B44 CN3.B47 CN3.B49 CN4.1 CN4.2 GF1.A1 GF1.A4 GF1.A7 GF1.A12 GF1.A15 GF1.A18 GF1.A20 GF1.A23 GF1.A24 GF1.A27 GF1.A28 GF1.A31 GF1.A34 GF1.A37 GF1.A38 GF1.A41 GF1.A42 GF1.A45 GF1.A46 GF1.A49 GF1.A51 GF1.A54 GF1.A55 GF1.A58 GF1.A59 GF1.A62 GF1.A63 GF1.A66 GF1.A67 GF1.A70 GF1.A71 GF1.A74 GF1.A75 GF1.A78 GF1.A79 GF1.A82 GF1.A84 GF1.A87 GF1.A88 GF1.A91 GF1.A92 GF1.A95 GF1.A96 GF1.A99 GF1.A100 GF1.A103 GF1.A104 GF1.A107 GF1.A108 GF1.A111 GF1.A112 GF1.A115 GF1.B4 GF1.B7 GF1.B13 GF1.B16 GF1.B18 GF1.B21 GF1.B22 GF1.B25 GF1.B26 GF1.B29 GF1.B32 GF1.B35 GF1.B36 GF1.B39 GF1.B40 GF1.B43 GF1.B44 GF1.B47 GF1.B49 GF1.B52 GF1.B53 GF1.B56 GF1.B57 GF1.B60 GF1.B61 GF1.B64 GF1.B65 GF1.B68 GF1.B69 GF1.B72 GF1.B73 GF1.B76 GF1.B77 GF1.B80 GF1.B82 GF1.B85 GF1.B86 GF1.B89 GF1.B90 GF1.B93 GF1.B94 GF1.B97 GF1.B98 GF1.B101 GF1.B102 GF1.B105 GF1.B106 GF1.B109 GF1.B110 GF1.B113 H1.1 H2.1 H3.1 H3.2 H3.3 H3.4 H3.5 H3.6 H4.1 H4.2 H4.3 H4.4 H4.5 H4.6 PC790.2 PC792.2 PC793.2 PC794.2 PC795.2 PC836.2 PC904.2 PC905.2 PC906.2 PC907.2 PC908.2 PC909.2 PC911.2 PC941.2 PC942.1 PC1055.2 PD11.A PG64.2 PR36.2 PR347.1 PR642.2 PU54.23 R2.2 R7.2 R8.1 R9.1 R10.2 R11.1 R12.2 R24.2 R26.1 R27.1 R28.1 R33.2 R35.2 TC1.2 TC2.2 TC3.2 U1.1 U2.1 U8.3 U9.3 U10.10 U13.3
P3V3: C5.1 C6.1 C7.1 C14.1 C15.1 C16.1 C31.1 C32.1 C33.1 C34.1 C35.1 C36.1 CN1.A9 CN1.A10 CN1.B8 CN2.A9 CN2.A10 CN2.B8 CN3.A9 CN3.A10 CN3.B8 PC790.1 PC792.1 PC793.1 PC794.1 PC795.1 PC836.1 PC908.1 PC909.1 PC919.1 PD11.K PL49.2 PR633.1 TC2.1 TC3.1
P3V3_AUX: C8.1 C9.1 C17.1 C18.1 C20.1 C22.1 C24.2 C26.1 C27.1 C40.1 CN1.B10 CN2.B10 CN3.B10 GF1.B10 R13.2 R14.2 R15.2 R16.2 R17.2 R18.1 R19.1 R20.1 R21.1 R22.1 R23.1 R29.2 R30.2 R31.2 R36.1 R37.1 U8.5 U9.5 U10.20 U13.5
P3V3_EN: PC1055.1 PR36.1 PR540.2 PU54.2
P3V3_LL: PC917.2 PC918.1 PL49.1 PR640.1 PU54.6 PU54.7 PU54.8 PU54.9 PU54.10 PU54.11
P3V3_LL_R: PC485.1 PC919.2 PR640.2
P3V3_MB: GF1.A9 GF1.A10 GF1.B8
P3V3_MODE: PR2171.2 PR2172.1 PU54.20
P3V3_PG: PR347.2 PR441.1 PR2172.2 PU54.3 U9.2
P3V3_RF: PR3.2 PR4.2 PU54.22
P3V3_ROVP: PR817.1 PU54.5
P3V3_SNB: PC918.2 PR642.1
P3V3_TRIP: PR2.2 PU54.21
P3V3_VBST: PR481.1 PU54.4
P3V3_VBST_RC: PC917.1 PR481.2
P3V3_VDD: PC941.1 PR649.2 PU54.19
P3V3_VFB: PC485.2 PR635.2 PR638.1 PU54.1
P3V3_VFB_R: PR633.2 PR635.1
P3V3_VIN: PC904.1 PC905.1 PC906.1 PC907.1 PC911.1 PL50.2 PU54.12 PU54.13 PU54.14 PU54.15 PU54.16 PU54.17
P3V3_VREG: PC942.2 PR3.1 PR441.2 PU54.18
P12V: C10.1 C11.1 C12.1 C13.1 C23.1 C25.1 C28.1 C29.1 C30.1 CN2.A2 CN2.A3 CN2.B1 CN2.B2 CN2.B3 CN3.A2 CN3.A3 CN3.B1 CN3.B2 CN3.B3 CN4.3 CN4.4 PL50.1 PR540.1 PR649.1 R5.1 TC1.1
P12V_MB: C1.1 C2.1 C3.1 C4.1 C21.1 CN1.A2 CN1.A3 CN1.B1 CN1.B2 CN1.B3 GF1.A2 GF1.A3 GF1.B1 GF1.B2 GF1.B3 R1.1
ADDR_0: R28.2 R29.1 U10.1
ADDR_1: R27.2 R30.1 U10.2
ADDR_2: R26.2 R31.1 U10.3
CLK100_PCIE_SLOT0_N: CN1.A14 GF1.A14
CLK100_PCIE_SLOT0_P: CN1.A13 GF1.A13
CLK100_PCIE_SLOT1_N: CN2.A14 GF1.A33
CLK100_PCIE_SLOT1_P: CN2.A13 GF1.A32
CLK100_PCIE_SLOT2_N: CN3.A14 GF1.A6
CLK100_PCIE_SLOT2_P: CN3.A13 GF1.A5
INTRPT: R17.1 U10.17
INTRPT_0: R13.1 U10.4
INTRPT_1: R14.1 U10.7
INTRPT_2: R15.1 U10.11
INTRPT_3: R16.1 U10.14
LAN_SMB_ALERT_N: GF1.B12 RE4.2 RE5.2 RE11.2
LAN_SMB_CLK: GF1.B9 RE2.1 RE9.1 RE14.1
LAN_SMB_DAT: GF1.A8 RE3.1 RE10.1 RE15.1
PCH_PLTRST_N: GF1.A11 U13.2
PCIE_SLOT0_CPRSNT1_N: CN1.B17 CN1.B31 GF1.B17
PCIE_SLOT0_CPRSNT2_N: CN1.B48 GF1.B31
PCIE_SLOT0_RXN0: CN1.A17 GF1.A17
PCIE_SLOT0_RXN1: CN1.A22 GF1.A22
PCIE_SLOT0_RXN2: CN1.A26 GF1.A26
PCIE_SLOT0_RXN3: CN1.A30 GF1.A30
PCIE_SLOT0_RXN4: CN1.A36 GF1.A36
PCIE_SLOT0_RXN5: CN1.A40 GF1.A40
PCIE_SLOT0_RXN6: CN1.A44 GF1.A44
PCIE_SLOT0_RXN7: CN1.A48 GF1.A48
PCIE_SLOT0_RXP0: CN1.A16 GF1.A16
PCIE_SLOT0_RXP1: CN1.A21 GF1.A21
PCIE_SLOT0_RXP2: CN1.A25 GF1.A25
PCIE_SLOT0_RXP3: CN1.A29 GF1.A29
PCIE_SLOT0_RXP4: CN1.A35 GF1.A35
PCIE_SLOT0_RXP5: CN1.A39 GF1.A39
PCIE_SLOT0_RXP6: CN1.A43 GF1.A43
PCIE_SLOT0_RXP7: CN1.A47 GF1.A47
PCIE_SLOT0_TXN0: CN1.B15 GF1.B15
PCIE_SLOT0_TXN1: CN1.B20 GF1.B20
PCIE_SLOT0_TXN2: CN1.B24 GF1.B24
PCIE_SLOT0_TXN3: CN1.B28 GF1.B28
PCIE_SLOT0_TXN4: CN1.B34 GF1.B34
PCIE_SLOT0_TXN5: CN1.B38 GF1.B38
PCIE_SLOT0_TXN6: CN1.B42 GF1.B42
PCIE_SLOT0_TXN7: CN1.B46 GF1.B46
PCIE_SLOT0_TXP0: CN1.B14 GF1.B14
PCIE_SLOT0_TXP1: CN1.B19 GF1.B19
PCIE_SLOT0_TXP2: CN1.B23 GF1.B23
PCIE_SLOT0_TXP3: CN1.B27 GF1.B27
PCIE_SLOT0_TXP4: CN1.B33 GF1.B33
PCIE_SLOT0_TXP5: CN1.B37 GF1.B37
PCIE_SLOT0_TXP6: CN1.B41 GF1.B41
PCIE_SLOT0_TXP7: CN1.B45 GF1.B45
PCIE_SLOT1_CPRSNT1_N: CN2.B17 CN2.B31 GF1.B48
PCIE_SLOT1_CPRSNT2_N: CN2.B48 GF1.B81
PCIE_SLOT1_RXN0: CN2.A17 GF1.A53
PCIE_SLOT1_RXN1: CN2.A22 GF1.A57
PCIE_SLOT1_RXN2: CN2.A26 GF1.A61
PCIE_SLOT1_RXN3: CN2.A30 GF1.A65
PCIE_SLOT1_RXN4: CN2.A36 GF1.A69
PCIE_SLOT1_RXN5: CN2.A40 GF1.A73
PCIE_SLOT1_RXN6: CN2.A44 GF1.A77
PCIE_SLOT1_RXN7: CN2.A48 GF1.A81
PCIE_SLOT1_RXP0: CN2.A16 GF1.A52
PCIE_SLOT1_RXP1: CN2.A21 GF1.A56
PCIE_SLOT1_RXP2: CN2.A25 GF1.A60
PCIE_SLOT1_RXP3: CN2.A29 GF1.A64
PCIE_SLOT1_RXP4: CN2.A35 GF1.A68
PCIE_SLOT1_RXP5: CN2.A39 GF1.A72
PCIE_SLOT1_RXP6: CN2.A43 GF1.A76
PCIE_SLOT1_RXP7: CN2.A47 GF1.A80
PCIE_SLOT1_TXN0: CN2.B15 GF1.B51
PCIE_SLOT1_TXN1: CN2.B20 GF1.B55
PCIE_SLOT1_TXN2: CN2.B24 GF1.B59
PCIE_SLOT1_TXN3: CN2.B28 GF1.B63
PCIE_SLOT1_TXN4: CN2.B34 GF1.B67
PCIE_SLOT1_TXN5: CN2.B38 GF1.B71
PCIE_SLOT1_TXN6: CN2.B42 GF1.B75
PCIE_SLOT1_TXN7: CN2.B46 GF1.B79
PCIE_SLOT1_TXP0: CN2.B14 GF1.B50
PCIE_SLOT1_TXP1: CN2.B19 GF1.B54
PCIE_SLOT1_TXP2: CN2.B23 GF1.B58
PCIE_SLOT1_TXP3: CN2.B27 GF1.B62
PCIE_SLOT1_TXP4: CN2.B33 GF1.B66
PCIE_SLOT1_TXP5: CN2.B37 GF1.B70
PCIE_SLOT1_TXP6: CN2.B41 GF1.B74
PCIE_SLOT1_TXP7: CN2.B45 GF1.B78
PCIE_SLOT2_CPRSNT1_N: CN3.B17 CN3.B31 GF1.B114
PCIE_SLOT2_CPRSNT2_N: CN3.B48 GF1.B115
PCIE_SLOT2_RXN0: CN3.A17 GF1.A86
PCIE_SLOT2_RXN1: CN3.A22 GF1.A90
PCIE_SLOT2_RXN2: CN3.A26 GF1.A94
PCIE_SLOT2_RXN3: CN3.A30 GF1.A98
PCIE_SLOT2_RXN4: CN3.A36 GF1.A102
PCIE_SLOT2_RXN5: CN3.A40 GF1.A106
PCIE_SLOT2_RXN6: CN3.A44 GF1.A110
PCIE_SLOT2_RXN7: CN3.A48 GF1.A114
PCIE_SLOT2_RXP0: CN3.A16 GF1.A85
PCIE_SLOT2_RXP1: CN3.A21 GF1.A89
PCIE_SLOT2_RXP2: CN3.A25 GF1.A93
PCIE_SLOT2_RXP3: CN3.A29 GF1.A97
PCIE_SLOT2_RXP4: CN3.A35 GF1.A101
PCIE_SLOT2_RXP5: CN3.A39 GF1.A105
PCIE_SLOT2_RXP6: CN3.A43 GF1.A109
PCIE_SLOT2_RXP7: CN3.A47 GF1.A113
PCIE_SLOT2_TXN0: CN3.B15 GF1.B84
PCIE_SLOT2_TXN1: CN3.B20 GF1.B88
PCIE_SLOT2_TXN2: CN3.B24 GF1.B92
PCIE_SLOT2_TXN3: CN3.B28 GF1.B96
PCIE_SLOT2_TXN4: CN3.B34 GF1.B100
PCIE_SLOT2_TXN5: CN3.B38 GF1.B104
PCIE_SLOT2_TXN6: CN3.B42 GF1.B108
PCIE_SLOT2_TXN7: CN3.B46 GF1.B112
PCIE_SLOT2_TXP0: CN3.B14 GF1.B83
PCIE_SLOT2_TXP1: CN3.B19 GF1.B87
PCIE_SLOT2_TXP2: CN3.B23 GF1.B91
PCIE_SLOT2_TXP3: CN3.B27 GF1.B95
PCIE_SLOT2_TXP4: CN3.B33 GF1.B99
PCIE_SLOT2_TXP5: CN3.B37 GF1.B103
PCIE_SLOT2_TXP6: CN3.B41 GF1.B107
PCIE_SLOT2_TXP7: CN3.B45 GF1.B111
PCIE_SMCLK: GF1.B5 U10.18
PCIE_SMCLK0: R18.2 RE1.2 U10.6
PCIE_SMCLK1: R19.2 RE6.2 U10.9
PCIE_SMCLK2: R20.2 RE12.2 U10.13
PCIE_SMDAT: GF1.B6 U10.19
PCIE_SMDAT0: R21.2 RE7.2 U10.5
PCIE_SMDAT1: R22.2 RE8.2 U10.8
PCIE_SMDAT2: R23.2 RE13.2 U10.12
PCIE_WAKE_N: CN1.B11 CN2.B11 CN3.B11 GF1.B11
PERST_O_1_R: R3.2 R37.2 U8.1
PERST_O_2_R: R4.2 R36.2 U9.1
PERST_P12V_MB_Y_N: R41.1 U8.4
PERST_P12V_R_N: R41.2 R42.2 U13.1
PERST_P12V_Y_N: R42.1 U8.2 U9.4
PERST_SLOT0_N: CN1.A11 R39.2
PERST_SLOT1_N: CN2.A11 R38.2
PERST_SLOT2_N: CN3.A11 R40.2
PERST_SLOT_N: R38.1 R39.1 R40.1 U13.4
RESET_O_1: R3.1 U1.2
RESET_O_2: R4.1 U2.2
RESET_P12V_IN: C37.1 R5.2 R24.1 U2.3
RESET_P12V_MB_IN: C19.1 R1.2 R2.1 U1.3
RSVD0: GF1.B30 TP6.1
RSVD1: GF1.A19 TP7.1
S0_PCIE_SMCLK: CN1.B5 RE1.1
S0_PCIE_SMDAT: CN1.B6 RE7.1
S0_SMB_ALERT_B12_N: CN1.B12 RE4.1
S0_SMB_CLK_A32: CN1.A32 RE2.2
S0_SMB_DAT_A33: CN1.A33 RE3.2
S1_PCIE_SMCLK: CN2.B5 RE6.1
S1_PCIE_SMDAT: CN2.B6 RE8.1
S1_SMB_ALERT_B12_N: CN2.B12 RE5.1
S1_SMB_CLK_A32: CN2.A32 RE9.2
S1_SMB_DAT_A33: CN2.A33 RE10.2
S2_PCIE_SMCLK: CN3.B5 RE12.1
S2_PCIE_SMDAT: CN3.B6 RE13.1
S2_SMB_ALERT_B12_N: CN3.B12 RE11.1
S2_SMB_CLK_A32: CN3.A32 RE14.2
S2_SMB_DAT_A33: CN3.A33 RE15.2
SLOT0_CONFIG: GF1.A50 R33.1
SLOT0_ID_0: CN1.A19 R7.1
SLOT0_ID_1: CN1.B30 R8.2
SLOT1_CONFIG: GF1.A83 R35.1
SLOT1_ID_0: CN2.A19 R10.1
SLOT1_ID_1: CN2.B30 R9.2
SLOT2_ID_0: CN3.A19 R12.1
SLOT2_ID_1: CN3.B30 R11.2

Pads without a net: CN1 A5 A6 A7 A8 B9; CN2 A5 A6 A7 A8 B9; CN3 A5 A6 A7 A8 B9; U10 15 16

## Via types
v1: diameter 0.559, hole 0.305, TOP to BOTTOM, 257 vias
v2: diameter 0.711, hole 0.356, TOP to BOTTOM, 16 vias
v3: diameter 0.711, hole 0.406, TOP to BOTTOM, 49 vias

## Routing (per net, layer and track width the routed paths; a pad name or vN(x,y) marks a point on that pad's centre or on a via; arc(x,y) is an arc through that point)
AGND_P3V3: length 31.1
  TOP w0.406: PR638.2 106.9,71.93 v1(107.2,72.22)
  TOP w0.508: PR4.1 110.88,70.83 109.48,72.22 PG64.1 v1(107.2,72.22) ; PR2171.1 PR2.1 v1(113.14,72.61) ; PR817.2 101.64,64.83 100.93,64.83 v1(100.85,64.91)
  BOTTOM w0.508: v1(100.85,64.91) 100.44,64.91 98.54,66.81 98.54,70.35 100.41,72.22 v1(107.2,72.22) 107.3,72.12 v2(109.91,72.12) 112.66,72.12 v1(113.14,72.61)
GND: length 759.6
  TOP w0.305: U13.3 17.67,37.38 v1(18.34,36.71) ; U9.3 v1(9.13,74.9) ; U10.10 v1(11.31,51.05)
  TOP w0.356: U8.3 22.45,24.07 v1(22.45,24.83)
  TOP w0.406: R9.1 55.82,45.99 v1(55.92,45.89)
  TOP w0.508: R7.2 39.26,23.26 v1(39.03,23.03) ; R11.1 55.58,65.85 v1(54.63,65.85) ; v1(33.09,68.04) 32.9,67.85 C26.2 33.93,66.05 C27.2 ; PR347.1 102.92,67.97 102.93,67.98 103.44,67.98 v1(103.54,68.08) ; C3.2 v1(15.45,31.89) ; R24.2 C37.2 ; C37.2 17.65,70.07 C23.2 ; C37.2 v1(16.67,71.11) ; C20.2 v1(18.45,21.25) ; R12.2 42.96,66.26 v1(44.21,66.26) ; v1(100.77,70.9) 100.91,70.76 PC1055.2 ; C4.2 v1(15.45,30.83) ; R35.2 v1(94.19,16.01) ; R10.2 41.39,44.72 41.8,44.32 v1(41.8,44.26) ; v1(20.22,16.47) 20.22,15.88 C21.2 ; v1(52.32,24.01) 53.23,24.01 R8.1 ; C8.2 v1(27.24,23.33) ; v1(103.64,70.85) 103.51,70.73 102.69,70.73 PR36.2 ; v1(12.75,43.52) 12.78,43.55 R26.1 ; C18.2 33.16,46.02 v1(33.39,45.79) 33.49,45.68 C17.2 ; v1(117.05,67.65) 116.26,67.65 PC942.1 ; C22.2 13.11,74.35 v1(12.32,75.14) ; v1(24.71,64.63) 24.71,64.59 C30.2 C29.2 ; C12.2 v1(15.03,52.8) ; U1.1 22.78,16.74 v1(22.78,15.73) ; C24.1 3.73,41.16 3.76,41.13 v1(3.76,40.77) ; C9.2 28.72,24.86 v1(28.59,24.99) ; R28.1 v1(9.16,40.84) ; v1(17.32,18.65) C19.2 R2.2 ; C2.2 v1(15.45,32.93) ; R33.2 72.58,24 v1(72.64,24) ; C25.2 C28.2 15.74,64.41 v1(15.86,64.29) ; C11.2 15.08,51.53 v1(15.05,51.55) ; R27.1 v1(7.06,40.83) ; C10.2 15.03,54.07 v1(15,54.04) ; C13.2 v1(15.03,55.34) ; C40.2 v1(18.24,42.12) ; U2.1 v1(17.78,76.39) ; PC941.2 v1(120.58,70.83) ; C1.2 v1(15.48,34)
  TOP w0.711: v1(28.19,6.89) 28.19,6.58 28.65,6.12 GF1.B16 ; GF1.B53 65.65,6.48 v1(66.23,7.06) ; GF1.B49 v1(61.65,6.89) ; v1(74.11,6.89) 74.11,6.81 73.65,6.35 GF1.B61 ; v1(37.08,6.89) 37.08,6.7 37.65,6.13 GF1.B25 ; GF1.B56 68.65,6.38 v1(68.14,6.89) ; GF1.B4 14.65,5.97 15.38,6.7 v1(15.38,7.04) ; GF1.B57 69.65,6.41 v1(70.07,6.94) ; v1(103.14,6.91) 103.14,6.78 102.65,6.29 GF1.B90 ; v1(86.12,6.89) 85.72,6.49 85.65,6.49 GF1.B73 ; GF1.B13 25.65,6.81 v1(25.65,7.9) ; v1(92.14,6.89) 92.14,6.84 92.65,6.33 GF1.B80 ; GF1.B68 80.65,6.29 80.1,6.83 v1(80.1,6.89) ; GF1.B36 48.65,6.42 49.03,6.8 v1(49.03,6.89) ; v1(90.21,6.89) 89.65,6.32 GF1.B77 ; v1(123.05,7.22) 122.65,6.81 GF1.B110 ; GF1.B89 101.65,6.39 v1(101.06,6.99) ; GF1.B85 97.65,6.48 v1(97.12,7.01) ; v1(111.07,6.96) 110.65,6.55 GF1.B98 ; GF1.B86 98.65,6.56 v1(99.05,6.96) ; GF1.B72 84.65,6.3 84.09,6.86 v1(84.09,6.89) ; GF1.B40 52.65,6.28 v1(53.36,6.99) ; GF1.B106 118.65,6.6 v1(119.17,7.11) ; v1(88.03,6.89) 88.65,6.26 GF1.B76 ; v1(109.08,7.19) 109.65,6.62 GF1.B97 ; v1(47.26,6.96) 47.65,6.57 GF1.B35 ; v1(125.01,7.14) 125.01,6.68 125.65,6.04 GF1.B113 ; GF1.B109 121.65,6.97 v1(121.23,7.39) ; GF1.B18 v1(30.65,6.89) ; GF1.B65 77.65,6.46 77.7,6.46 v1(78.12,6.89) ; GF1.B52 64.65,6.29 v1(64.05,6.89) ; v1(51.02,6.89) 51.64,6.27 51.65,6.27 GF1.B39 ; v1(55.32,6.89) 55.65,6.56 GF1.B43 ; v1(113.17,7.11) 113.17,7.16 113.65,6.69 GF1.B101 ; GF1.B69 81.65,6.32 82.08,6.76 v1(82.08,6.89) ; v1(72.18,6.89) 72.58,6.49 72.65,6.49 GF1.B60 ; v1(115.23,6.94) 114.65,6.35 GF1.B102 ; GF1.B22 34.65,6.23 35.12,6.69 v1(35.12,6.89) ; v1(105.27,6.94) 105.65,6.56 GF1.B93 ; GF1.B7 v1(17.65,6.91) ; v1(44.24,6.96) 44.65,6.55 GF1.B32 ; GF1.B26 38.65,6.28 39.03,6.66 v1(39.03,6.89) ; v1(57.09,6.89) 56.65,6.45 GF1.B44 ; v1(59.22,6.89) 59.65,6.46 GF1.B47 ; GF1.B64 76.65,6.4 76.19,6.86 v1(76.19,6.89) ; GF1.B21 33.65,6.22 v1(32.99,6.89) ; v1(107.15,7.14) 106.65,6.63 GF1.B94 ; GF1.B29 41.65,6.43 v1(41.19,6.89) ; v1(117.19,7.16) 117.65,6.7 GF1.B105 ; GF1.B82 v1(94.65,6.89)
  L3 w0.457: CN1.B26 49.98,27.98 ; CN1.B26 49.09,28.86 ; CN1.B26 49.09,27.09 ; CN1.B26 48.2,27.98 ; 3,28.23 H3.5 3.79,29.02 ; 59.2,32.47 CN1.A37 ; CN1.A37 60.98,32.47 ; CN1.A37 60.09,33.36 ; CN1.A37 60.09,31.59 ; CN1.A41 64.09,33.36 ; CN1.A41 63.2,32.47 ; CN1.A41 64.09,31.59 ; CN1.A41 64.98,32.47 ; 2.66,26.96 H3.6 3.45,26.17 ; CN1.B36 59.98,27.98 ; CN1.B36 59.09,27.09 ; CN1.B36 58.2,27.98 ; CN1.B36 59.09,28.86 ; CN1.A12 35.09,35.36 ; CN1.A12 35.09,33.59 ; CN1.A12 35.98,34.47 ; CN1.A12 34.2,34.47 ; 51.2,29.98 CN1.B29 ; CN1.B29 52.09,29.09 ; CN1.B29 52.98,29.98 ; CN1.B29 52.09,30.86 ; CN1.B25 48.98,29.98 ; CN1.B25 47.2,29.98 ; CN1.B25 48.09,29.09 ; CN1.B25 48.09,30.86 ; 57.2,29.98 CN1.B35 ; CN1.B35 58.09,30.86 ; CN1.B35 58.98,29.98 ; CN1.B35 58.09,29.09 ; 136.3,28.23 H4.2 135.51,29.02 ; CN1.A20 43.09,35.36 ; CN1.A20 43.09,33.59 ; CN1.A20 42.2,34.47 ; CN1.A20 43.98,34.47 ; 61.09,33.59 CN1.A38 ; CN1.A38 60.2,34.47 ; CN1.A38 61.09,35.36 ; CN1.A38 61.98,34.47 ; 44.09,29.09 CN1.B21 ; CN1.B21 43.2,29.98 ; CN1.B21 44.98,29.98 ; CN1.B21 44.09,30.86 ; CN1.A46 69.98,34.47 ; CN1.A46 69.09,33.59 ; CN1.A46 68.2,34.47 ; CN1.A46 69.09,35.36 ; 71.2,32.47 CN1.A49 ; CN1.A49 72.09,31.59 ; CN1.A49 72.09,33.36 ; CN1.A34 57.98,34.47 ; CN1.A34 57.09,33.59 ; CN1.A34 57.09,35.36 ; CN1.A34 56.2,34.47 ; CN1.B39 62.98,29.98 ; CN1.B39 62.09,30.86 ; CN1.B39 62.09,29.09 ; CN1.B39 61.2,29.98 ; CN1.B16 39.09,28.86 ; CN1.B16 39.09,27.09 ; CN1.B16 39.98,27.98 ; CN1.B16 38.2,27.98 ; CN1.B47 70.09,30.86 ; CN1.B47 70.09,29.09 ; CN1.B47 69.2,29.98 ; CN1.B47 70.98,29.98 ; 65.2,29.98 CN1.B43 ; CN1.B43 66.09,30.86 ; CN1.B43 66.98,29.98 ; CN1.B43 66.09,29.09 ; 132.02,29.96 H4.4 131.23,29.17 ; H1.1 6,66.34 ; H1.1 2.62,62.96 ; H1.1 6,59.58 ; H1.1 9.38,62.96 ; CN1.B32 55.09,28.86 ; CN1.B32 55.09,27.09 ; CN1.B32 55.98,27.98 ; CN1.B32 54.2,27.98 ; 46.2,34.47 CN1.A24 ; CN1.A24 47.09,35.36 ; CN1.A24 47.09,33.59 ; CN1.A24 47.98,34.47 ; CN1.A31 54.98,32.47 ; CN1.A31 53.2,32.47 ; CN1.A31 54.09,31.59 ; CN1.A31 54.09,33.36 ; CN1.A27 50.98,32.47 ; CN1.A27 49.2,32.47 ; CN1.A27 50.09,31.59 ; CN1.A27 50.09,33.36 ; CN1.A42 65.98,34.47 ; CN1.A42 65.09,35.36 ; CN1.A42 64.2,34.47 ; CN1.A42 65.09,33.59 ; 3.93,29.17 H3.4 4.72,29.96 ; CN1.B18 41.09,28.86 ; CN1.B18 40.2,27.98 ; CN1.B18 41.98,27.98 ; CN1.B18 41.09,27.09 ; 62.2,27.98 CN1.B40 ; CN1.B40 63.09,27.09 ; CN1.B40 63.98,27.98 ; CN1.B40 63.09,28.86 ; 129.96,26.96 H4.6 130.75,26.17 ; CN1.B44 67.98,27.98 ; CN1.B44 67.09,28.86 ; CN1.B44 67.09,27.09 ; CN1.B44 66.2,27.98 ; 71.2,29.98 CN1.B49 ; CN1.B49 72.09,30.86 ; CN1.B49 72.09,29.09 ; 68.09,31.59 CN1.A45 ; CN1.A45 68.09,33.36 ; CN1.A45 68.98,32.47 ; CN1.A45 67.2,32.47 ; 130.3,28.23 H4.5 131.09,29.02 ; 50.2,34.47 CN1.A28 ; CN1.A28 51.98,34.47 ; CN1.A28 51.09,33.59 ; CN1.A28 51.09,35.36 ; 7.27,29.96 H3.3 8.06,29.17 ; CN1.A23 46.98,32.47 ; CN1.A23 45.2,32.47 ; CN1.A23 46.09,33.36 ; CN1.A23 46.09,31.59 ; CN1.B22 45.98,27.98 ; CN1.B22 44.2,27.98 ; CN1.B22 45.09,28.86 ; CN1.B22 45.09,27.09 ; 40.2,34.47 CN1.A18 ; CN1.A18 41.09,33.59 ; CN1.A18 41.09,35.36 ; CN1.A18 41.98,34.47 ; 8.21,29.02 H3.2 9,28.23 ; 135.85,26.17 H4.1 136.64,26.96 ; 134.57,29.96 H4.3 135.36,29.17 ; 38.09,31.59 CN1.A15 ; CN1.A15 37.2,32.47 ; CN1.A15 38.98,32.47 ; CN1.A15 38.09,33.36 ; CN1.B13 36.98,29.98 ; CN1.B13 36.09,30.86 ; CN1.B13 35.2,29.98 ; CN1.B13 36.09,29.09 ; 8.55,26.17 H3.1 9.34,26.96
  L4 w0.457: CN1.B39 62.98,29.98 ; CN1.B39 62.09,29.09 ; CN1.B39 61.2,29.98 ; CN1.B39 62.09,30.86 ; 58.09,29.09 CN1.B35 ; CN1.B35 57.2,29.98 ; CN1.B35 58.09,30.86 ; CN1.B35 58.98,29.98 ; 48.09,29.09 CN1.B25 ; CN1.B25 48.09,30.86 ; CN1.B25 47.2,29.98 ; CN1.B25 48.98,29.98 ; H2.1 133.3,71.34 ; H2.1 136.68,67.96 ; H2.1 133.3,64.58 ; H2.1 129.92,67.96 ; CN1.A18 41.09,35.36 ; CN1.A18 41.09,33.59 ; CN1.A18 40.2,34.47 ; CN1.A18 41.98,34.47 ; 51.2,29.98 CN1.B29 ; CN1.B29 52.09,29.09 ; CN1.B29 52.09,30.86 ; CN1.B29 52.98,29.98 ; 21.2,53.48 CN2.A1 ; CN2.A1 22.09,52.59 ; CN2.A1 22.98,53.48 ; CN2.A1 22.09,54.36 ; 25.09,69.09 CN3.B4 ; CN3.B4 25.09,70.86 ; CN3.B4 24.2,69.98 ; 58.2,27.98 CN1.B36 ; CN1.B36 59.09,27.09 ; CN1.B36 59.09,28.86 ; CN1.B36 59.98,27.98 ; 71.2,29.98 CN1.B49 ; CN1.B49 72.09,30.86 ; CN1.B49 72.09,29.09 ; CN1.A23 46.09,33.36 ; CN1.A23 46.98,32.47 ; CN1.A23 46.09,31.59 ; CN1.A23 45.2,32.47 ; 69.09,33.59 CN1.A46 ; CN1.A46 69.09,35.36 ; CN1.A46 69.98,34.47 ; CN1.A46 68.2,34.47 ; 44.2,27.98 CN1.B22 ; CN1.B22 45.09,27.09 ; CN1.B22 45.09,28.86 ; CN1.B22 45.98,27.98 ; CN1.B21 44.98,29.98 ; CN1.B21 44.09,29.09 ; CN1.B21 43.2,29.98 ; CN1.B21 44.09,30.86 ; 125.4,49.16 CN4.1 ; CN4.1 125.4,52.44 ; CN4.1 127.04,50.8 ; CN4.1 123.76,50.8 ; 25.09,75.59 CN3.A4 ; CN3.A4 24.2,76.48 ; CN3.A4 25.09,77.36 ; 72.09,31.59 CN1.A49 ; CN1.A49 71.2,32.47 ; CN1.A49 72.09,33.36 ; 67.2,32.47 CN1.A45 ; CN1.A45 68.09,31.59 ; CN1.A45 68.98,32.47 ; CN1.A45 68.09,33.36 ; CN3.A1 22.09,75.36 ; CN3.A1 22.09,73.59 ; CN3.A1 22.98,74.48 ; CN3.A1 21.2,74.48 ; 60.09,31.59 CN1.A37 ; CN1.A37 59.2,32.47 ; CN1.A37 60.98,32.47 ; CN1.A37 60.09,33.36 ; 130.75,26.17 H4.6 129.96,26.96 ; 131.09,29.02 H4.5 130.3,28.23 ; 47.09,33.59 CN1.A24 ; CN1.A24 47.98,34.47 ; CN1.A24 46.2,34.47 ; CN1.A24 47.09,35.36 ; 51.09,33.59 CN1.A28 ; CN1.A28 50.2,34.47 ; CN1.A28 51.09,35.36 ; CN1.A28 51.98,34.47 ; CN1.B44 67.09,28.86 ; CN1.B44 66.2,27.98 ; CN1.B44 67.98,27.98 ; CN1.B44 67.09,27.09 ; 50.09,31.59 CN1.A27 ; CN1.A27 49.2,32.47 ; CN1.A27 50.09,33.36 ; CN1.A27 50.98,32.47 ; CN1.A34 57.98,34.47 ; CN1.A34 57.09,35.36 ; CN1.A34 56.2,34.47 ; CN1.A34 57.09,33.59 ; CN4.2 127.04,46.6 ; CN4.2 123.76,46.6 ; CN4.2 125.4,44.96 ; CN4.2 125.4,48.24 ; 24.2,48.98 CN2.B4 ; CN2.B4 25.09,49.86 ; CN2.B4 25.09,48.09 ; CN1.B47 70.98,29.98 ; CN1.B47 69.2,29.98 ; CN1.B47 70.09,29.09 ; CN1.B47 70.09,30.86 ; CN1.B43 66.98,29.98 ; CN1.B43 65.2,29.98 ; CN1.B43 66.09,29.09 ; CN1.B43 66.09,30.86 ; CN1.A15 38.98,32.47 ; CN1.A15 38.09,33.36 ; CN1.A15 38.09,31.59 ; CN1.B16 39.98,27.98 ; CN1.B16 39.09,28.86 ; CN1.B16 39.09,27.09 ; CN1.B16 38.2,27.98 ; 24.2,55.48 CN2.A4 ; CN2.A4 25.09,56.36 ; CN2.A4 25.09,54.59 ; 8.21,29.02 H3.2 9,28.23 ; H1.1 9.38,62.96 ; H1.1 6,59.58 ; H1.1 6,66.34 ; H1.1 2.62,62.96 ; 136.3,28.23 H4.2 135.51,29.02 ; 62.2,27.98 CN1.B40 ; CN1.B40 63.98,27.98 ; CN1.B40 63.09,27.09 ; CN1.B40 63.09,28.86 ; CN1.A31 54.09,33.36 ; CN1.A31 54.98,32.47 ; CN1.A31 54.09,31.59 ; CN1.A31 53.2,32.47 ; 131.23,29.17 H4.4 132.02,29.96 ; CN1.B18 41.09,28.86 ; CN1.B18 41.98,27.98 ; CN1.B18 40.2,27.98 ; CN1.B18 41.09,27.09 ; 8.55,26.17 H3.1 9.34,26.96 ; 135.36,29.17 H4.3 134.57,29.96 ; CN1.A38 61.09,35.36 ; CN1.A38 60.2,34.47 ; CN1.A38 61.98,34.47 ; CN1.A38 61.09,33.59 ; CN1.B32 55.98,27.98 ; CN1.B32 55.09,28.86 ; CN1.B32 54.2,27.98 ; CN1.B32 55.09,27.09 ; 3.93,29.17 H3.4 4.72,29.96 ; 3,28.23 H3.5 3.79,29.02 ; 64.09,31.59 CN1.A41 ; CN1.A41 63.2,32.47 ; CN1.A41 64.09,33.36 ; CN1.A41 64.98,32.47 ; 8.06,29.17 H3.3 7.27,29.96 ; CN1.A42 65.98,34.47 ; CN1.A42 64.2,34.47 ; CN1.A42 65.09,35.36 ; CN1.A42 65.09,33.59 ; CN1.A20 43.98,34.47 ; CN1.A20 43.09,35.36 ; CN1.A20 43.09,33.59 ; CN1.A20 42.2,34.47 ; 136.64,26.96 H4.1 135.85,26.17 ; CN1.B26 49.09,28.86 ; CN1.B26 49.09,27.09 ; CN1.B26 48.2,27.98 ; CN1.B26 49.98,27.98 ; 2.66,26.96 H3.6 3.45,26.17
  BOTTOM w0.508: GF1.A1 11.65,6.68 12.06,7.09 12.06,9.38 v1(12.27,9.58)
  BOTTOM w0.711: GF1.A88 100.65,6.58 v1(101.06,6.99) ; v1(41.19,6.89) 40.65,6.35 GF1.A28 ; GF1.A75 87.65,6.3 88.03,6.68 v1(88.03,6.89) ; v1(119.17,7.11) 119.65,6.63 GF1.A107 ; GF1.A74 86.65,6.38 86.63,6.38 v1(86.12,6.89) ; v1(39.03,6.89) 39.65,6.27 GF1.A27 ; v1(44.24,6.96) 43.65,6.37 GF1.A31 ; v1(37.08,6.89) 37.08,6.63 36.65,6.21 GF1.A24 ; GF1.A112 124.65,6.63 125.01,6.99 v1(125.01,7.14) ; GF1.A63 75.65,6.32 76.19,6.86 v1(76.19,6.89) ; v1(72.18,6.89) 71.72,6.43 71.65,6.43 GF1.A59 ; GF1.A91 103.65,6.4 v1(103.14,6.91) ; GF1.A67 79.65,6.28 80.1,6.73 v1(80.1,6.89) ; GF1.A58 70.65,6.36 v1(70.07,6.94) ; GF1.A70 82.65,6.29 82.08,6.86 v1(82.08,6.89) ; v1(59.22,6.89) 58.69,6.36 58.65,6.36 GF1.A46 ; GF1.A84 96.65,6.54 v1(97.12,7.01) ; GF1.A15 27.65,6.1 28.19,6.63 v1(28.19,6.89) ; GF1.A111 123.65,6.62 v1(123.05,7.22) ; v1(49.03,6.89) 49.61,6.3 49.65,6.3 GF1.A37 ; GF1.A87 99.65,6.36 v1(99.05,6.96) ; v1(105.27,6.94) 104.65,6.31 GF1.A92 ; GF1.A115 127.65,6.23 127.16,6.72 v1(127.16,7.46) ; v1(51.02,6.89) 51.02,6.63 50.65,6.26 GF1.A38 ; GF1.A82 v1(94.65,6.89) ; GF1.A18 v1(30.65,6.89) ; GF1.A41 53.7,3.55 53.7,6.64 v1(53.36,6.99) ; v1(78.12,6.89) 78.12,6.88 78.65,6.36 GF1.A66 ; v1(121.23,7.39) 120.65,6.82 GF1.A108 ; v1(113.17,7.11) 112.65,6.59 GF1.A100 ; v1(32.99,6.89) 32.99,6.58 32.65,6.24 GF1.A20 ; v1(57.09,6.89) 57.65,6.33 GF1.A45 ; v1(107.15,7.14) 107.26,7.14 107.65,6.74 GF1.A95 ; GF1.A71 83.65,6.47 83.67,6.47 v1(84.09,6.89) ; GF1.A62 74.65,6.27 74.11,6.81 v1(74.11,6.89) ; v1(25.65,7.9) 24.65,6.91 GF1.A12 ; GF1.A34 46.65,6.35 v1(47.26,6.96) ; v1(15.38,7.04) 15.38,6.66 14.65,5.92 GF1.A4 ; v1(64.05,6.89) 64.05,6.61 63.65,6.21 GF1.A51 ; GF1.A96 108.65,6.76 v1(109.08,7.19) ; GF1.A7 v1(17.65,6.91) ; GF1.A42 54.65,6.21 v1(55.32,6.89) ; GF1.A103 115.65,6.52 v1(115.23,6.94) ; GF1.A55 67.65,6.29 68.14,6.78 v1(68.14,6.89) ; v1(117.19,7.16) 116.65,6.63 GF1.A104 ; v1(90.21,6.89) 90.21,6.88 90.65,6.45 GF1.A78 ; GF1.A54 66.65,6.65 v1(66.23,7.06) ; GF1.A79 91.65,6.24 92.14,6.73 v1(92.14,6.89) ; GF1.A23 35.65,6.25 35.12,6.78 v1(35.12,6.89) ; GF1.A99 111.65,6.38 v1(111.07,6.96) ; GF1.A49 v1(61.65,6.89)
  vias: v1(3.68,72.19) v1(3.94,74.89) v1(3.89,69.07) v1(7.06,74.84) v1(7.06,72.09) v1(9.98,69.93) v1(11.63,66.81) v1(26.59,63.72) v1(26.59,62.73) v1(26.59,61.82) v1(26.59,60.75) v1(33.6,40.86) v1(33.65,38.83) v1(44.98,45.5) v1(77.9,50.5) v1(78.43,75.63) v1(79.7,72.26) v1(80.94,75.71) v1(82.85,72.23) v1(84.04,75.76) v1(86.13,72.17) v1(87.27,75.79) v1(88.04,68.92) v1(89.03,64.68) v1(90.25,72.17) v1(90.47,75.76) v1(90.88,34.58) v1(91.74,68.94) v1(91.9,61.15) v1(92,31.28) v1(92.38,27.41) v1(92.74,64.7) v1(92.91,23.71) v1(93.7,75.68) v1(93.88,20.1) v1(93.95,72.19) v1(94.74,17.18) v1(95.61,61.17) v1(95.66,56.9) v1(97.2,75.73) v1(103.37,75.68) v1(106.57,75.66) v1(106.61,70.29) v1(107.3,67.04) v1(107.53,70.29) v1(108.31,68.87) v1(108.34,67.07) v1(108.29,65.59) v1(108.29,64.48) v1(108.44,70.29) v1(109.38,70.29) v1(109.43,67.04) v1(109.37,43.21) v1(109.81,75.58) v1(110.21,60.54) v1(111.79,58.97) v1(111.84,40.44) v1(113.31,75.63) v1(113.68,36.06) v1(113.88,58.97) v1(114.66,22.13) v1(114.81,42.88) v1(114.88,28.53) v1(115.64,33.24) v1(115.85,75.57) v1(115.97,37.2) v1(116.06,59) v1(116.13,54.03) v1(116.15,52.08) v1(116.23,49.69) v1(116.23,47.1) v1(117.09,19.39) v1(117.91,24.67) v1(118.08,29.74) v1(118.22,58.97) v1(118.52,73.21) v1(119.42,33.49) v1(119.55,40.68) v1(119.94,36.71) v1(120.09,16.64) v1(120.26,26.59) v1(120.8,22.28) v1(120.95,43.43) v1(121.41,75.01) v1(122.68,13.47) v1(122.9,29.02) v1(122.98,32.56) v1(123.38,39.01) v1(123.38,24.83) v1(123.46,42.64) v1(123.69,35.93) v1(123.72,21.56) v1(124.18,18.09) v1(124.74,10.93) v1(124.93,67.73) v1(124.92,55.2) v1(125.24,72.18) v1(125.17,60.41) v1(125.52,75.05) v1(125.65,23.63) v1(126.74,16.3) v1(127.07,56.86) v1(127.32,31.89) v1(127.37,38.19) v1(127.45,35.12) v1(127.66,63.3) v1(127.75,40.71) v1(130.4,74.74) v1(135.09,74.47) v3(16.78,62.07) v3(16.76,59.12) v3(17.95,62.1) v3(18,59.12) v3(19.14,62.1) v3(19.24,59.12) v3(22.85,40.96) v3(22.88,38.02) v3(24.05,40.99) v3(23.97,38.04) v3(25.11,41.01) v3(25.06,38.07) v3(36.67,59.17) v3(37.84,59.15)
P3V3: length 35.5
  TOP w0.864: PC919.1 PR633.1
  TOP w1.016: PR633.1 v1(96.4,73.85)
  L4 w0.457: 28.2,48.98 CN2.B8 ; CN2.B8 29.09,49.86 ; CN2.B8 29.98,48.98 ; CN2.B8 29.09,48.09 ; 30.09,52.59 CN2.A9 ; CN2.A9 30.09,54.36 ; CN2.A9 30.98,53.48 ; CN2.A9 29.2,53.48 ; 29.09,27.09 CN1.B8 ; CN1.B8 29.09,28.86 ; CN1.B8 29.98,27.98 ; CN1.B8 28.2,27.98 ; 28.2,69.98 CN3.B8 ; CN3.B8 29.09,69.09 ; CN3.B8 29.98,69.98 ; CN3.B8 29.09,70.86 ; CN3.A10 31.98,76.48 ; CN3.A10 31.09,75.59 ; CN3.A10 31.09,77.36 ; CN3.A10 30.2,76.48 ; CN1.A10 31.98,34.47 ; CN1.A10 30.2,34.47 ; CN1.A10 31.09,33.59 ; CN1.A10 31.09,35.36 ; 30.09,73.59 CN3.A9 ; CN3.A9 30.98,74.48 ; CN3.A9 29.2,74.48 ; CN3.A9 30.09,75.36 ; 30.09,31.59 CN1.A9 ; CN1.A9 30.98,32.47 ; CN1.A9 29.2,32.47 ; CN1.A9 30.09,33.36 ; CN2.A10 31.09,56.36 ; CN2.A10 31.09,54.59 ; CN2.A10 31.98,55.48 ; CN2.A10 30.2,55.48
  vias: v3(27.47,41.01) v3(27.58,38.07) v3(28.74,41.06) v3(28.87,38.07) v3(30.12,41.06) v3(30.19,38.09) v3(31.54,59.16) v3(31.87,62.15) v3(32.96,59.16) v3(33.09,62.15) v3(99.25,53.58) v3(100.31,53.56) v3(101.38,53.58) v3(102.47,53.56) v3(105.74,54.49) v3(106.65,50.6) v3(107.82,47.53) v3(108.08,54.52) v3(110.13,54.54) v3(111.53,52.48) v3(111.51,50.35) v3(112.12,54.29)
P3V3_AUX: length 67.9
  TOP w0.305: C40.1 16.71,40.77 16.37,40.42 U13.5 ; C24.2 3.23,43.1 3.23,44.89 3.54,45.2 U10.20
  TOP w0.406: C20.1 20.79,21.44 U8.5
  TOP w0.457: CN1.B10 31.09,28.86 ; CN1.B10 30.2,27.98 ; CN1.B10 31.98,27.98 ; CN1.B10 31.09,27.09
  TOP w0.508: R17.2 R16.2 v1(5.97,40.88) ; v1(14.04,43.46) R21.1 14.04,44.64 13.3,45.38 R31.2 R13.2 ; v1(17.22,42.14) 17.17,42.14 16.71,41.68 C40.1 ; C27.1 32.01,65.59 C26.1 ; v1(20.98,20.2) C20.1 21.11,21.38 R37.1 ; C17.1 31.56,44.89 31.54,44.91 31.54,45.8 C18.1 31.32,46.51 v1(30.88,46.96) ; R36.1 14.21,72.73 C22.1 12.9,72.52 11.82,72.52 11.55,72.79 U9.5 ; R30.2 v1(8.13,40.83) ; R15.2 5.26,53.21 R23.1 v1(5.26,54.32) ; R18.1 16.84,43.55 v1(16.87,43.52) ; v1(4.09,43.52) 4.09,42.95 C24.2 ; R19.1 v1(16.12,50.46) ; R22.1 16.17,46.74 v1(17.07,46.74) ; R20.1 8.07,53.2 R14.2 v1(9.13,54.27) ; R29.2 v1(10.21,40.88)
  TOP w0.61: CN3.B10 31.09,69.97 31.27,69.97 32.04,69.2 v1(32.04,67.96) 32.04,67.1 C26.1
  TOP w0.635: v1(14.45,56.27) 14.78,56.6 14.78,72.16 R36.1
  TOP w0.711: 20.65,7.01 GF1.B10
  L3 w0.457: 30.2,48.98 CN2.B10 ; CN2.B10 31.98,48.98 ; CN2.B10 31.09,48.09 ; CN2.B10 31.09,49.86 ; CN1.B10 31.09,28.86 ; CN1.B10 30.2,27.98 ; CN1.B10 31.09,27.09 ; CN1.B10 31.98,27.98
  vias: v3(21.69,14.05) v3(23.06,14.05) v3(32.31,24.49)
P3V3_EN: length 25.7
  TOP w0.178: v1(100.73,69.87) 100.75,69.86 101.65,69.86 PC1055.1 101.69,69.85 PR36.1 102.69,69.83 103.69,69.83 104.88,68.64 PU54.2 ; v1(115.68,69.68) 116.06,69.68 117.86,67.88 118.89,67.88 PR540.2
  BOTTOM w0.178: v1(115.68,69.68) 114.23,71.13 v2(112.05,71.13) 104.83,71.13 103.57,69.87 v1(100.73,69.87)
P3V3_LL: length 8.8
  TOP w0.508: PR640.1 96.96,70.32 96.51,69.87 v1(96.51,69.6)
  BOTTOM w0.635: v1(96.51,69.6) 95.73,68.83 95.73,65.38 v1(97.29,63.82)
P3V3_LL_R: length 3
  TOP w0.508: PC485.1 99.5,71.92 PC919.2 99.37,70.66 PR640.2
P3V3_MB: length 12
  TOP w0.711: v1(18.99,6.99) 18.65,6.65 GF1.B8
  BOTTOM w0.711: GF1.A9 19.65,6.06 18.99,6.72 v1(18.99,6.99) 20.11,6.99 20.65,6.44 GF1.A10
P3V3_MODE: length 20.1
  TOP w0.254: v1(100.77,68.03) 101.57,68.03 PR2172.1 ; PU54.20 112.7,68.14 113.88,69.31 v1(113.88,69.97) 114.14,70.24 114.14,70.32 114.41,70.59 PR2171.2
  BOTTOM w0.254: v1(113.88,69.97) 113.49,69.58 110.91,69.58 v2(110.88,69.61) 110.85,69.58 104.93,69.58 104.19,68.84 101.58,68.84 v1(100.77,68.03)
